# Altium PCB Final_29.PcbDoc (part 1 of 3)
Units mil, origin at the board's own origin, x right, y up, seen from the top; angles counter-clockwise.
Board outline 11000 x 6000 mil, 4 copper layers (TopLayer, MidLayer1, MidLayer2, BottomLayer), stack 29.222 mil thick; 209 components, 95 nets, 681 pads, 861 vias.
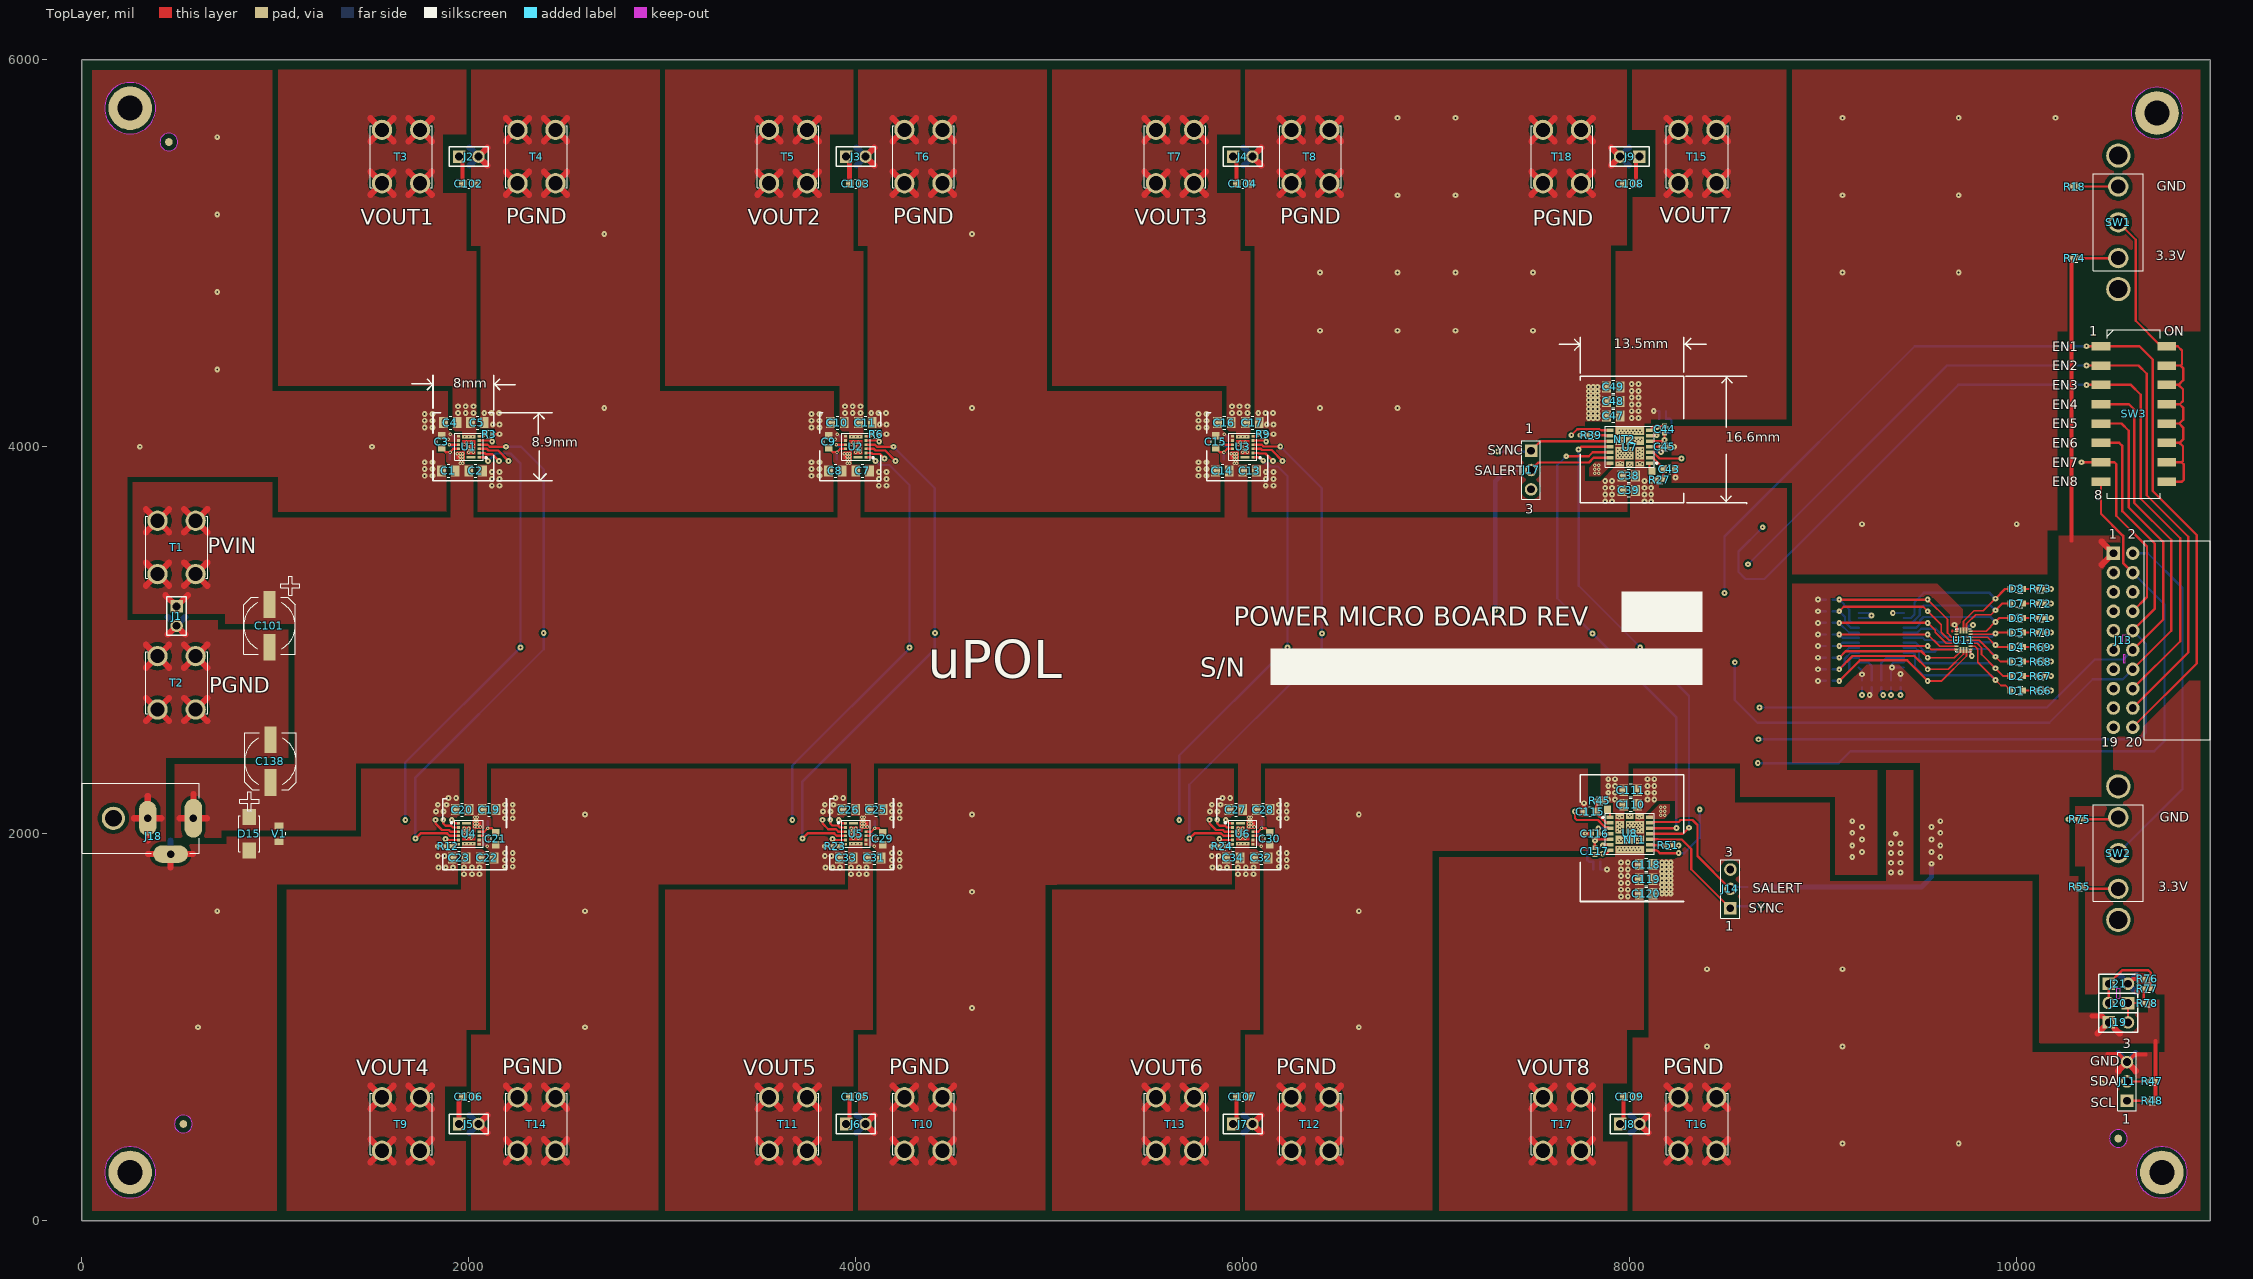
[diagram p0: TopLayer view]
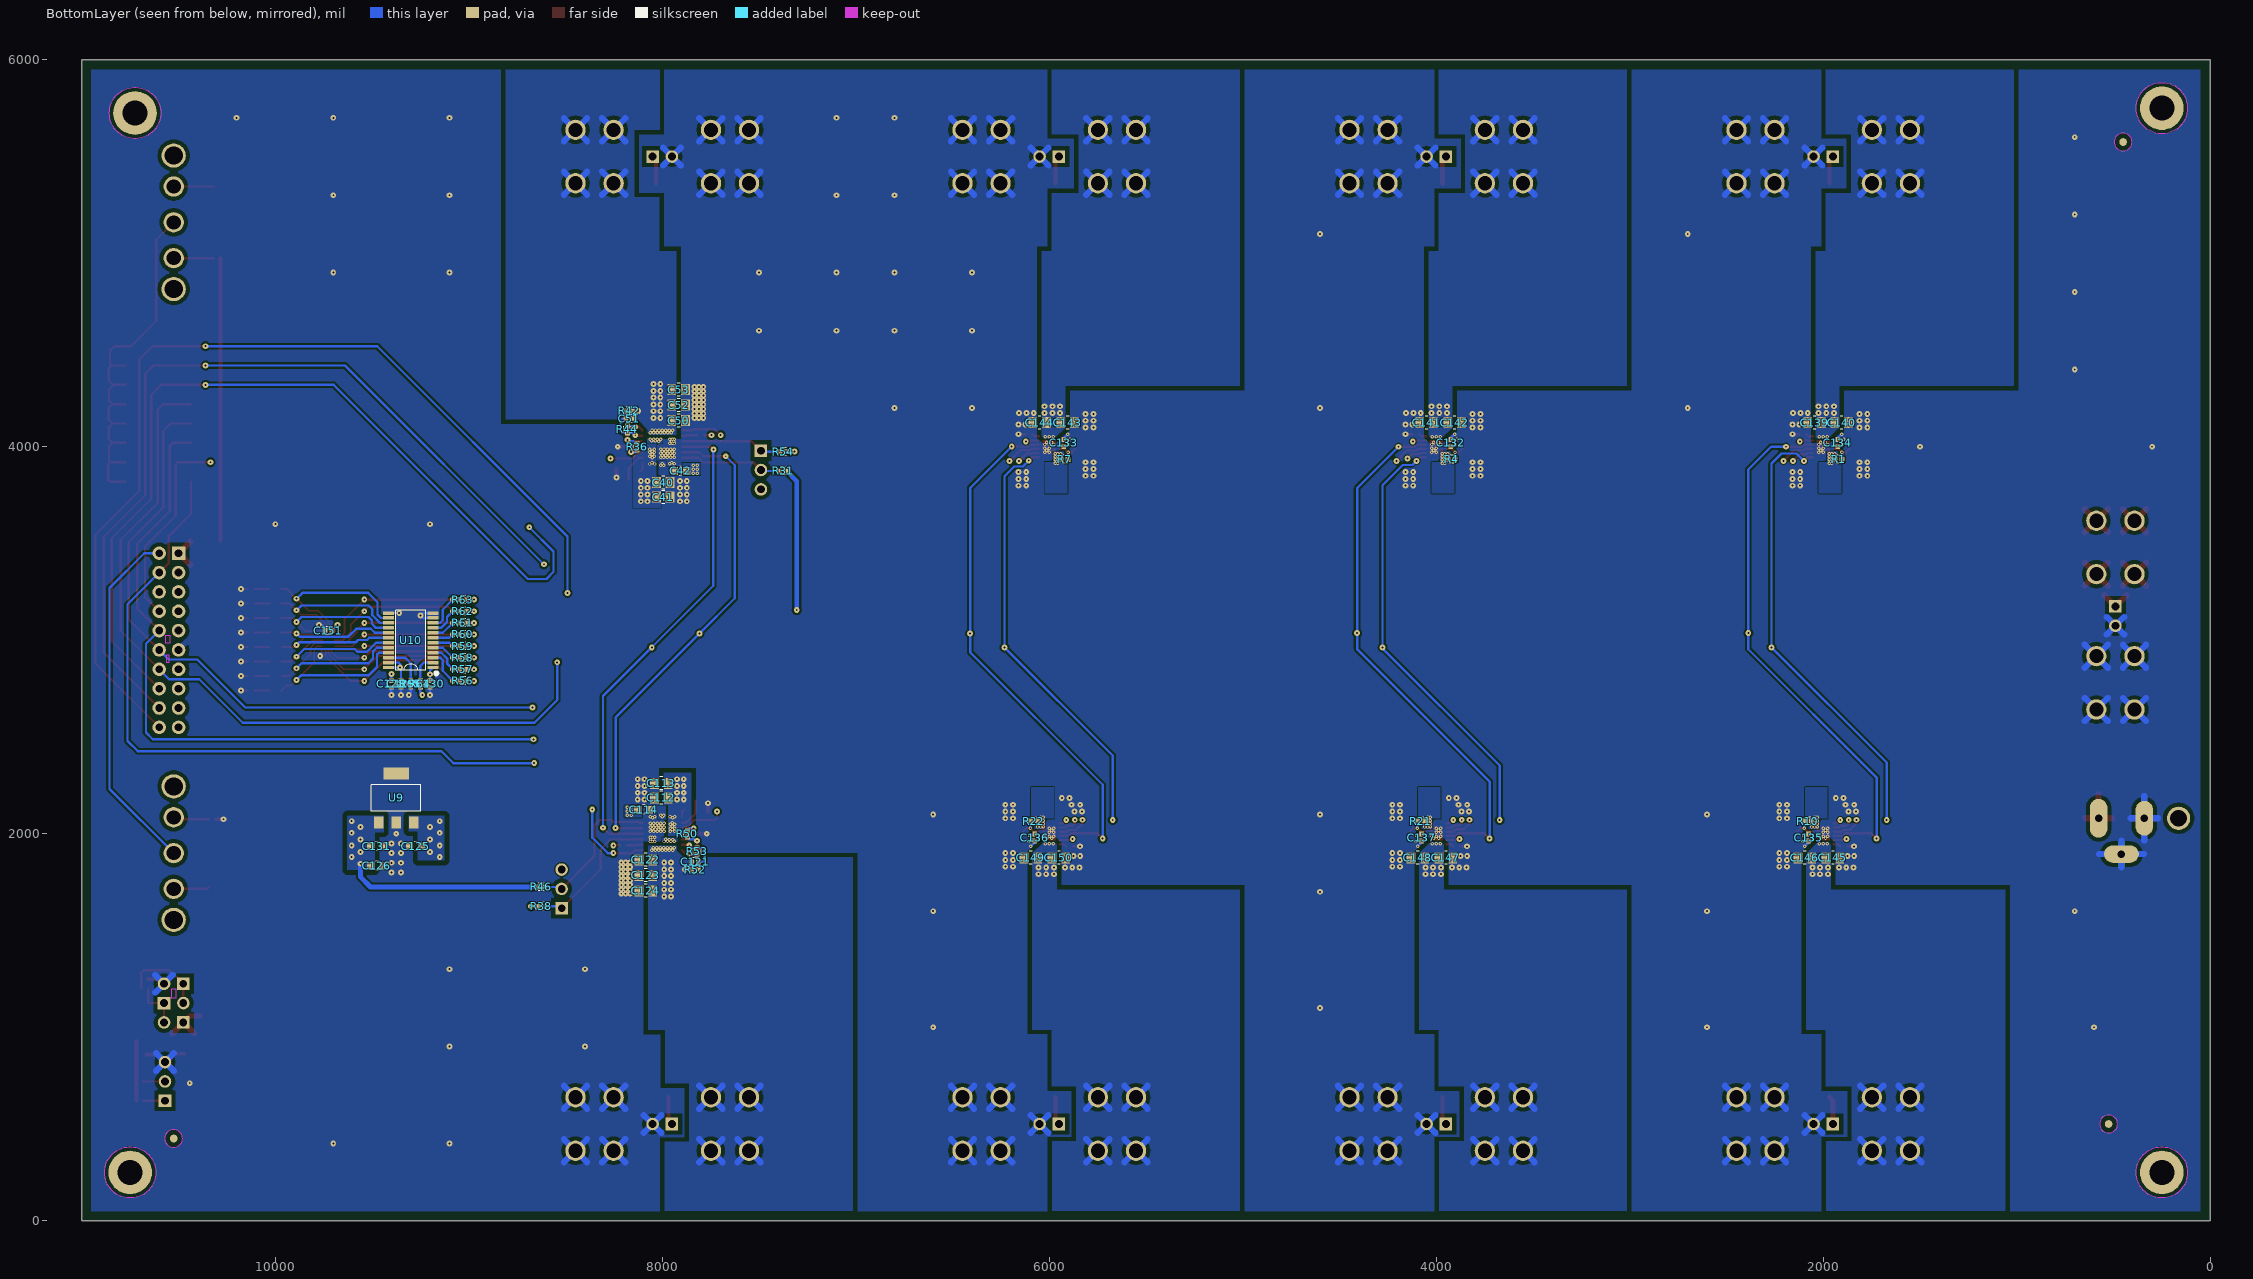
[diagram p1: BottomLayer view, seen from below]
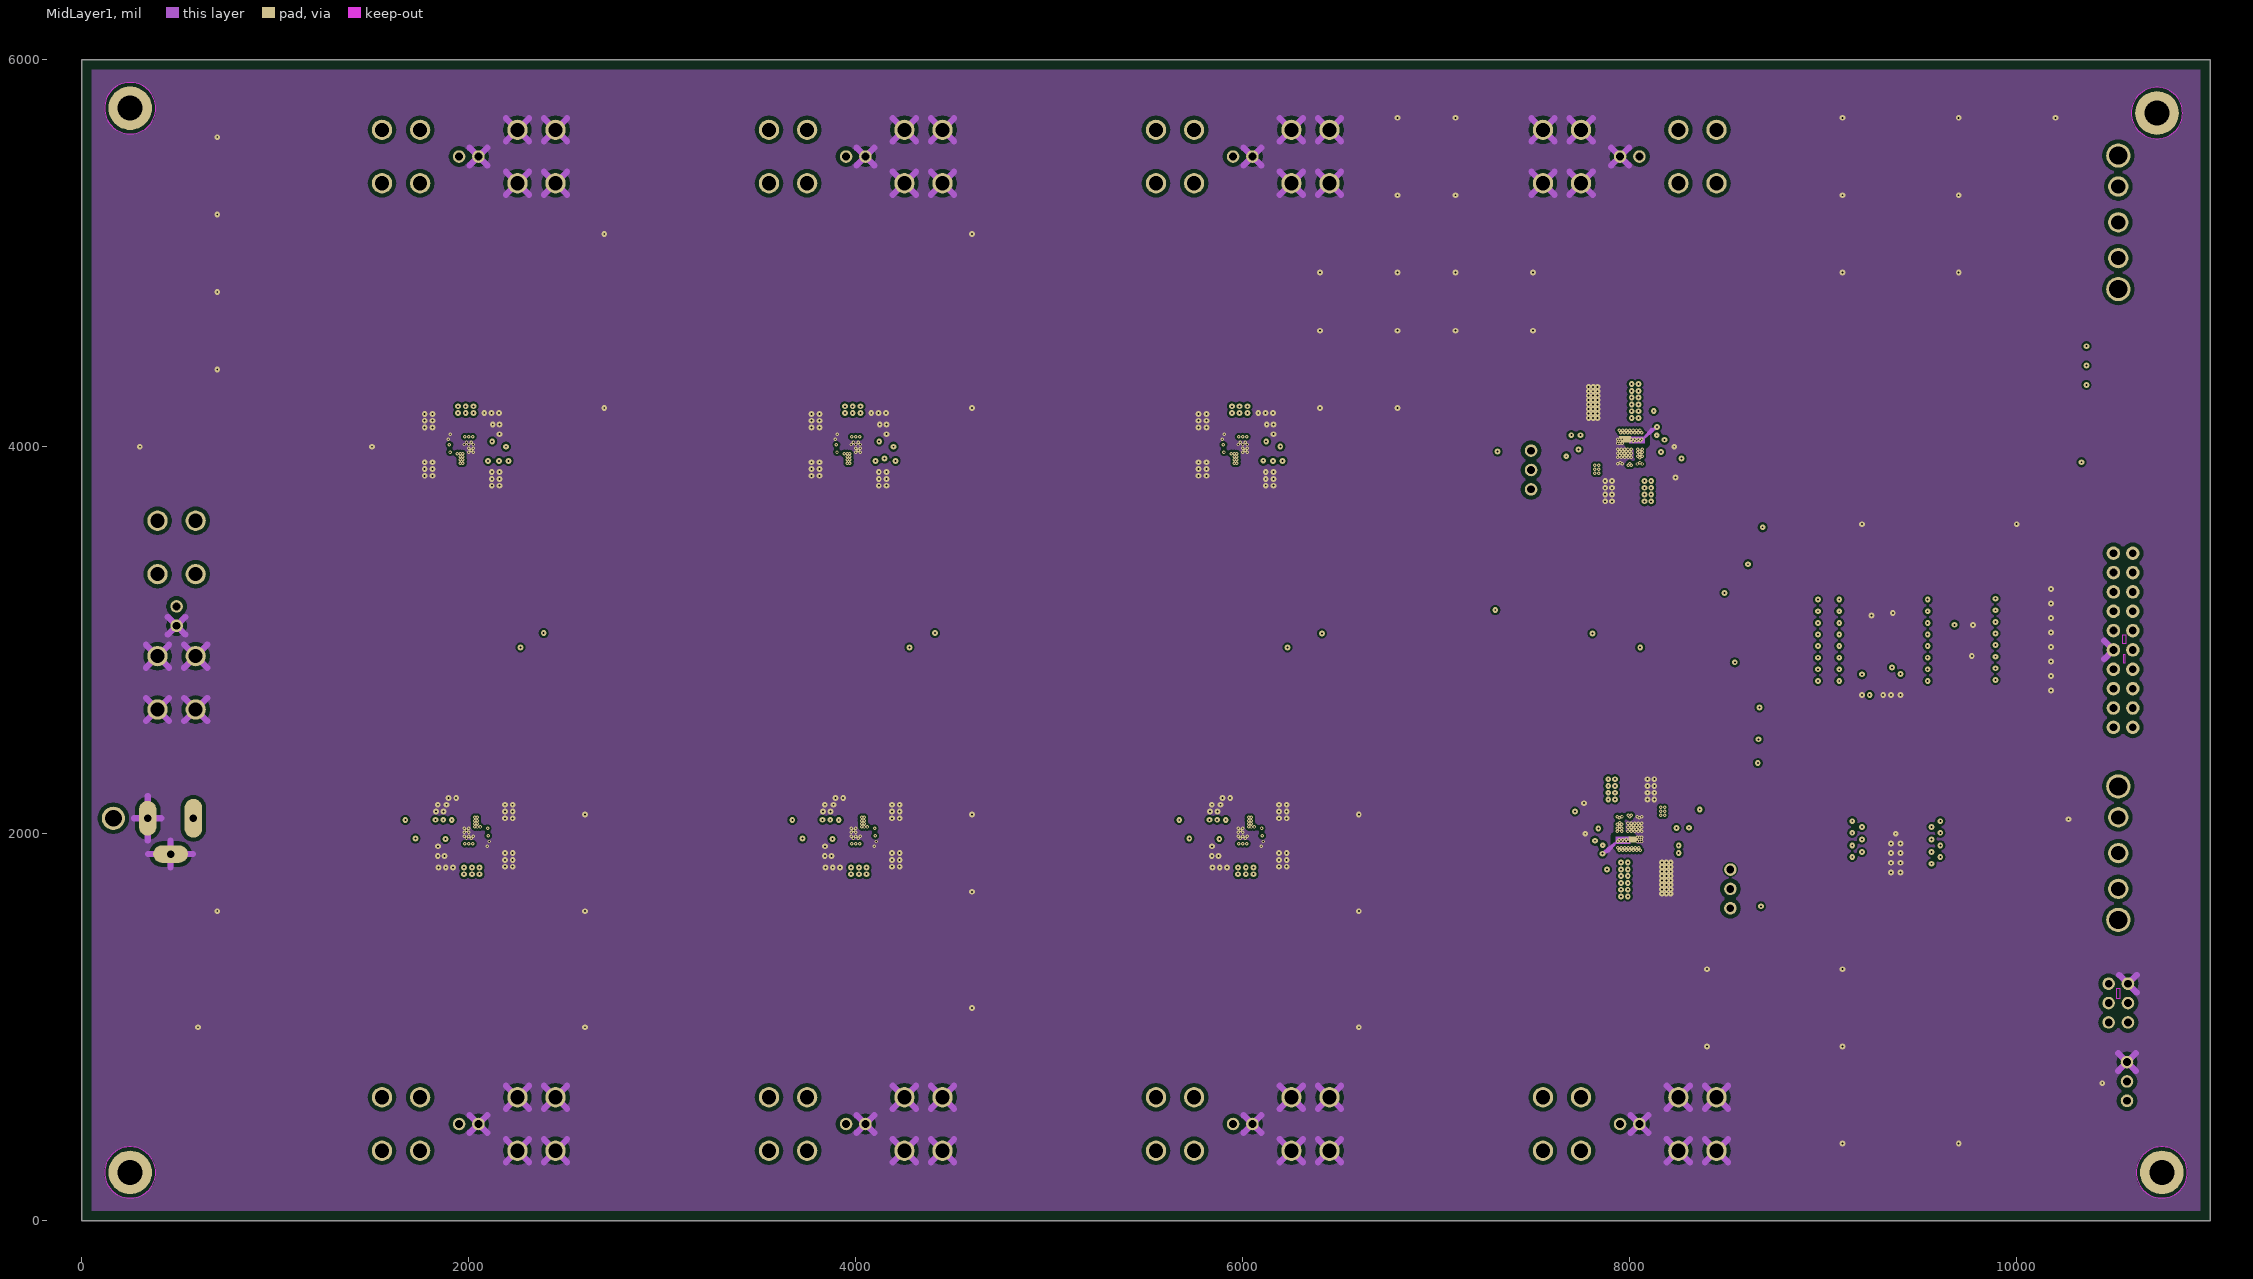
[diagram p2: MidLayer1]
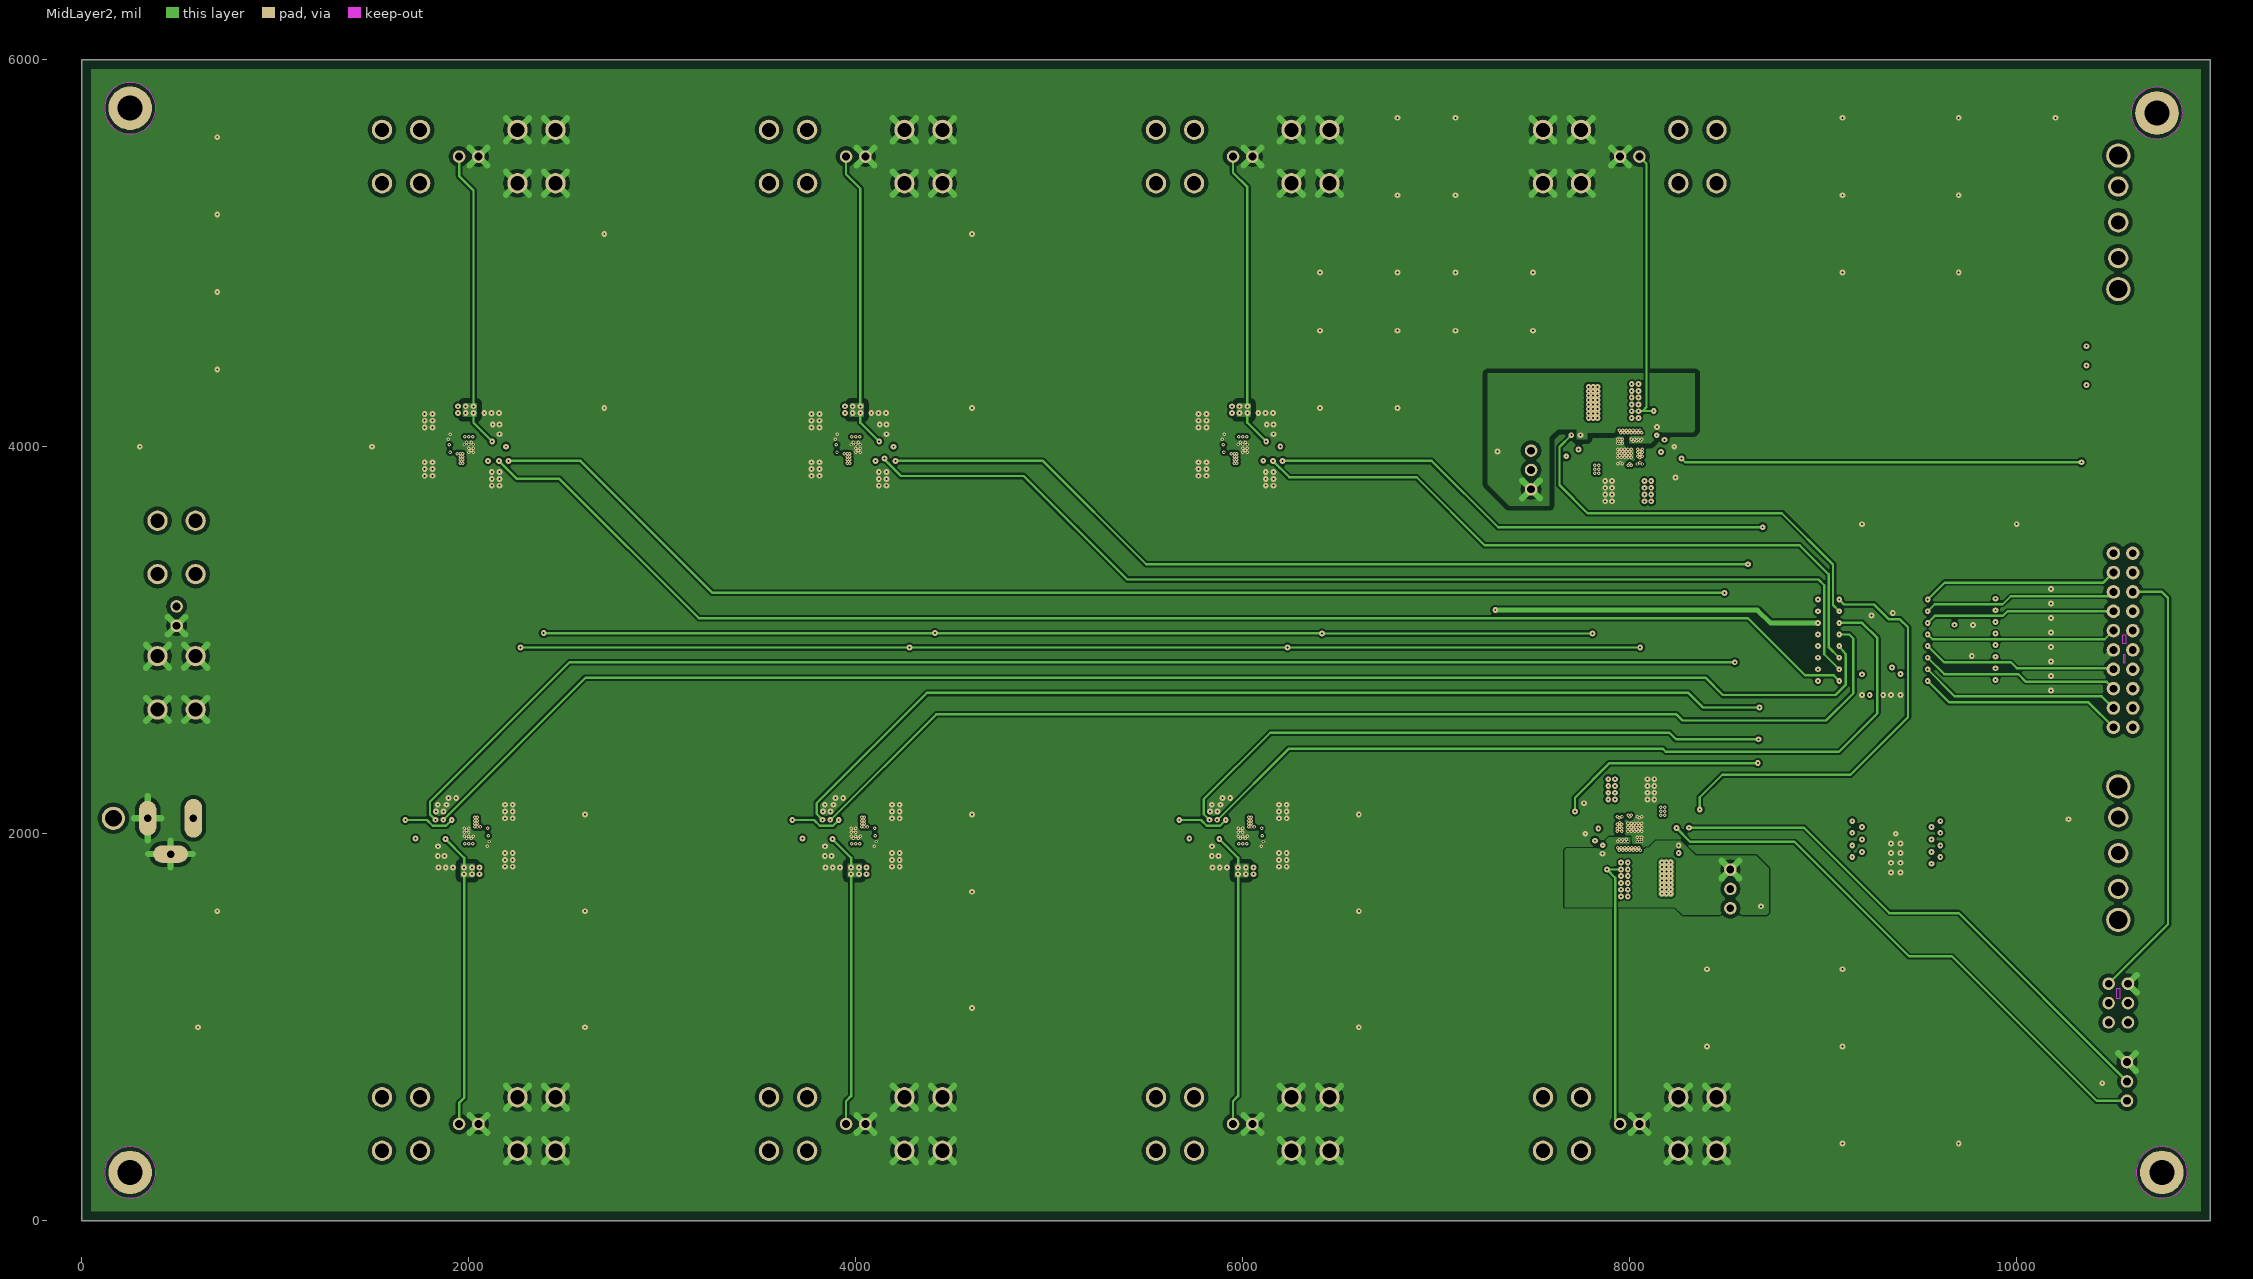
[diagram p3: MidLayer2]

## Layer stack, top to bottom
TopSolder: solder mask 0.4, Solder Resist, Dk 3.5
TopLayer: signal copper 1.4
Dielectric1: core 7.874, FR-4, Dk 4.8
MidLayer1: signal copper 1.4
Dielectric2: core 7.874, FR-4, Dk 4.8
MidLayer2: signal copper 1.4
Dielectric3: core 7.874, FR-4, Dk 4.8
BottomLayer: signal copper 1.4
BottomSolder: solder mask 0.4, Solder Resist, Dk 3.5

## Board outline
0,0 11000,0 11000,6000 0,6000

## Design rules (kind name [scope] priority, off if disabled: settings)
BoardOutlineClearance [All] p1: gap=5 ignorepadtopadclearanceinfootprint=FALSE except(0: Arc-SplitContinuation Track-SplitContinuation SMDPad-SplitContinuation THPad-SplitContinuation Via-SplitContinuation Fill-SplitContinuation Poly-SplitContinuation Region-SplitContinuation Text-SplitContinuation)
Clearance [(IsFill AND InNet('AGND1') or InNet('AGND2'))] p1: gap=6 ignorepadtopadclearanceinfootprint=TRUE except(0: Arc-Hole Track-Hole SMDPad-Hole THPad-Hole Via-Hole Fill-Hole Poly-Hole Region-Hole Text-Hole; 1: Via-Fill; 10: Via-Poly; 25: Fill-Poly)
Clearance Clearance_to_Keepout [iskeepout] p2: gap=0 ignorepadtopadclearanceinfootprint=FALSE
Clearance RELAX_TOP_Poly [Onlayer('TopLayer') vs (((WithInRoom('RELAX_AREA_1') or WithInRoom('RELAX_AREA_3') or WithInRoom('RELAX_AREA_5') or WithInRoom('RELAX_AREA_6') or WithInRoom('RELAX_AREA_7') or WithInRoom('RELAX_AREA_8') or WithInRoom('RELAX_AREA_9') or WithInRoom('RELAX_AREA_15') or WithInRoom('RELAX_AREA_17')) AND IsRegion) or ((TouchesRoom('RELAX_AREA_1') or TouchesRoom('RELAX_AREA_3') or TouchesRoom('RELAX_AREA_5') or TouchesRoom('RELAX_AREA_6') or TouchesRoom('RELAX_AREA_7') or TouchesRoom('RELAX_AREA_8') or TouchesRoom('RELAX_AREA_9') or TouchesRoom('RELAX_AREA_15') or TouchesRoom('RELAX_AREA_17')) AND InPoly))] p3 off: gap=5 ignorepadtopadclearanceinfootprint=FALSE except(0: Poly-Region; 15: THPad-Poly)
Clearance RELAX_TOP [Onlayer('TopLayer') vs (((WithInRoom('RELAX_AREA_1') or WithInRoom('RELAX_AREA_3') or WithInRoom('RELAX_AREA_5') or WithInRoom('RELAX_AREA_6') or WithInRoom('RELAX_AREA_7') or WithInRoom('RELAX_AREA_8') or WithInRoom('RELAX_AREA_9') or WithInRoom('RELAX_AREA_15') or WithInRoom('RELAX_AREA_17')) AND (InPoly = False)) or ((TouchesRoom('RELAX_AREA_1') or TouchesRoom('RELAX_AREA_3') or TouchesRoom('RELAX_AREA_5') or TouchesRoom('RELAX_AREA_6') or TouchesRoom('RELAX_AREA_7') or TouchesRoom('RELAX_AREA_8') or TouchesRoom('RELAX_AREA_9') or TouchesRoom('RELAX_AREA_15') or TouchesRoom('RELAX_AREA_17')) AND InPoly))] p4: gap=5 ignorepadtopadclearanceinfootprint=FALSE except(15: THPad-Poly)
Clearance RELAX_MID1_Poly [Onlayer('MidLayer1') vs (((WithInRoom('RELAX_AREA_17')) AND IsRegion) or ((TouchesRoom('RELAX_AREA_17')) AND InPoly))] p5: gap=8 ignorepadtopadclearanceinfootprint=FALSE except(0: Poly-Region; 10: Arc-Poly Arc-Region Track-Poly Track-Region SMDPad-Poly SMDPad-Region THPad-Region Via-Poly Via-Region Poly-Hole Region-Hole; 20: THPad-Poly; 25: Poly-Poly Region-Region)
Clearance RELAX_MID1 [Onlayer('MidLayer1') vs (((WithInRoom('RELAX_AREA_17')) AND (InPoly = False)) or ((TouchesRoom('RELAX_AREA_17')) AND InPoly))] p6: gap=8 ignorepadtopadclearanceinfootprint=FALSE except(10: Arc-Poly Arc-Region Track-Poly Track-Region SMDPad-Poly SMDPad-Region THPad-Region Via-Poly Via-Region Poly-Hole Region-Hole; 20: THPad-Poly; 25: Poly-Poly Poly-Region Region-Region)
Clearance RELAX_MID2_Poly [Onlayer('MidLayer2') vs (((WithInRoom('RELAX_AREA_17')) AND IsRegion) or ((TouchesRoom('RELAX_AREA_17')) AND InPoly))] p7: gap=8 ignorepadtopadclearanceinfootprint=FALSE except(0: Poly-Region; 10: Arc-Poly Arc-Region Track-Poly Track-Region SMDPad-Poly SMDPad-Region THPad-Region Via-Poly Via-Region Poly-Hole Region-Hole; 20: THPad-Poly; 25: Poly-Poly Region-Region)
Clearance RELAX_MID2 [Onlayer('MidLayer2') vs (((WithInRoom('RELAX_AREA_17')) AND (InPoly = False)) or ((TouchesRoom('RELAX_AREA_17')) AND InPoly))] p8: gap=8 ignorepadtopadclearanceinfootprint=FALSE except(10: Arc-Poly Arc-Region Track-Poly Track-Region SMDPad-Poly SMDPad-Region THPad-Region Via-Poly Via-Region Poly-Hole Region-Hole; 20: THPad-Poly; 25: Poly-Poly Poly-Region Region-Region)
Clearance RELAX_BOTTOM_Poly [Onlayer('BottomLayer') vs (((WithInRoom('RELAX_AREA_2') or WithInRoom('RELAX_AREA_4') or WithInRoom('RELAX_AREA_10') or WithInRoom('RELAX_AREA_11') or WithInRoom('RELAX_AREA_12') or WithInRoom('RELAX_AREA_13') or WithInRoom('RELAX_AREA_14') or WithInRoom('RELAX_AREA_16') or WithInRoom('RELAX_AREA_17')) AND IsRegion) or ((TouchesRoom('RELAX_AREA_2') or TouchesRoom('RELAX_AREA_4') or TouchesRoom('RELAX_AREA_10') or TouchesRoom('RELAX_AREA_11') or TouchesRoom('RELAX_AREA_12') or TouchesRoom('RELAX_AREA_13') or TouchesRoom('RELAX_AREA_14') or TouchesRoom('RELAX_AREA_16') or TouchesRoom('RELAX_AREA_17')) AND InPoly))] p9: gap=8 ignorepadtopadclearanceinfootprint=FALSE except(0: Poly-Region; 5: Arc-Poly Arc-Region Track-Poly Track-Region SMDPad-Poly SMDPad-Region THPad-Region Via-Poly Via-Region Poly-Poly Poly-Hole Region-Region Region-Hole; 15: THPad-Poly)
Clearance RELAX_BOTTOM [Onlayer('BottomLayer') vs (((WithInRoom('RELAX_AREA_2') or WithInRoom('RELAX_AREA_4') or WithInRoom('RELAX_AREA_10') or WithInRoom('RELAX_AREA_11') or WithInRoom('RELAX_AREA_12') or WithInRoom('RELAX_AREA_13') or WithInRoom('RELAX_AREA_14') or WithInRoom('RELAX_AREA_16') or WithInRoom('RELAX_AREA_17')) AND (InPoly = False)) or ((TouchesRoom('RELAX_AREA_2') or TouchesRoom('RELAX_AREA_4') or TouchesRoom('RELAX_AREA_10') or TouchesRoom('RELAX_AREA_11') or TouchesRoom('RELAX_AREA_12') or TouchesRoom('RELAX_AREA_13') or TouchesRoom('RELAX_AREA_14') or TouchesRoom('RELAX_AREA_16') or TouchesRoom('RELAX_AREA_17')) AND InPoly))] p10: gap=8 ignorepadtopadclearanceinfootprint=FALSE except(5: Arc-Poly Arc-Region Track-Poly Track-Region SMDPad-Poly SMDPad-Region THPad-Region Via-Poly Via-Region Poly-Poly Poly-Region Poly-Hole Region-Region Region-Hole; 15: THPad-Poly)
Clearance DEFAULT_TOP [InNetClass('DEFAULT') AND Onlayer('TopLayer')] p11: gap=8 ignorepadtopadclearanceinfootprint=FALSE except(6: SMDPad-SMDPad; 10: Arc-Poly Arc-Region Track-Poly Track-Region SMDPad-Poly SMDPad-Region THPad-Region Via-Poly Via-Region Poly-Hole Region-Hole; 20: THPad-Poly; 25: Poly-Poly Poly-Region Region-Region)
Clearance DEFAULT_MID1 [InNetClass('DEFAULT') AND Onlayer('MidLayer1')] p12: gap=8 ignorepadtopadclearanceinfootprint=FALSE except(6: SMDPad-SMDPad; 10: Arc-Poly Arc-Region Track-Poly Track-Region SMDPad-Poly SMDPad-Region THPad-Region Via-Poly Via-Region Poly-Hole Region-Hole; 20: THPad-Poly; 25: Poly-Poly Poly-Region Region-Region)
Clearance DEFAULT_MID2 [InNetClass('DEFAULT') AND Onlayer('MidLayer2')] p13: gap=8 ignorepadtopadclearanceinfootprint=FALSE except(6: SMDPad-SMDPad; 10: Arc-Poly Arc-Region Track-Poly Track-Region SMDPad-Poly SMDPad-Region THPad-Region Via-Poly Via-Region Poly-Hole Region-Hole; 20: THPad-Poly; 25: Poly-Poly Poly-Region Region-Region)
Clearance DEFAULT_BOTTOM [InNetClass('DEFAULT') AND Onlayer('BottomLayer')] p14: gap=8 ignorepadtopadclearanceinfootprint=FALSE except(6: SMDPad-SMDPad; 10: Arc-Poly Arc-Region Track-Poly Track-Region SMDPad-Poly SMDPad-Region THPad-Region Via-Poly Via-Region Poly-Hole Region-Hole; 20: THPad-Poly; 25: Poly-Poly Poly-Region Region-Region)
Clearance Clearance_default [All] p15: gap=6 ignorepadtopadclearanceinfootprint=FALSE except(0: Arc-Hole Track-Hole SMDPad-Hole THPad-Hole Via-Hole Fill-Hole Poly-Hole Region-Hole Text-Hole)
ComponentClearance Component_5mil_Clearance [All] p1: gap=0 collisioncheckmode=3 verticalgap=0 showdistances=TRUE
HoleSize [All] p1: absolutevalues=TRUE maxlimit=250 minlimit=8 maxpercent=80.000 minpercent=20.000
HoleToHoleClearance [All] p1: gap=25 allowstackedmicrovias=TRUE
MinimumAnnularRing [All] p1: minimumring=0
MinimumSolderMaskSliver [All] p1: minsoldermaskwidth=0
NetAntennae [All] p1 off: netantennaetolerance=0
PasteMaskExpansion [HasFootprint('No Footprint') And OnLayer('Top Layer')] p1: expansion=0
PolygonConnect PAD_J18-2_th_conn_TOP [(ObjectKind = 'Pad') AND (Name = 'J18-2') vs IsPoly AND Onlayer('TopLayer')] p1: connectstyle=Relief reliefconductorwidth=32 reliefentries=4 polygonreliefangle="90 Angle" airgapwidth=20
PolygonConnect PAD_J18-2_th_conn_L2 [(ObjectKind = 'Pad') AND (Name = 'J18-2') vs IsPoly AND Onlayer('MidLayer1')] p2: connectstyle=Relief reliefconductorwidth=32 reliefentries=4 polygonreliefangle="90 Angle" airgapwidth=20
PolygonConnect PAD_J18-2_th_conn_L3 [(ObjectKind = 'Pad') AND (Name = 'J18-2') vs IsPoly AND Onlayer('MidLayer2')] p3: connectstyle=Relief reliefconductorwidth=32 reliefentries=4 polygonreliefangle="90 Angle" airgapwidth=20
PolygonConnect PAD_J18-2_th_conn_BOTTOM [(ObjectKind = 'Pad') AND (Name = 'J18-2') vs IsPoly AND Onlayer('BottomLayer')] p4: connectstyle=Relief reliefconductorwidth=32 reliefentries=4 polygonreliefangle="90 Angle" airgapwidth=20
PolygonConnect PAD_J18-3_th_conn_TOP [(ObjectKind = 'Pad') AND (Name = 'J18-3') vs IsPoly AND Onlayer('TopLayer')] p5: connectstyle=Relief reliefconductorwidth=32 reliefentries=4 polygonreliefangle="90 Angle" airgapwidth=20
PolygonConnect PAD_J18-3_th_conn_L2 [(ObjectKind = 'Pad') AND (Name = 'J18-3') vs IsPoly AND Onlayer('MidLayer1')] p6: connectstyle=Relief reliefconductorwidth=32 reliefentries=4 polygonreliefangle="90 Angle" airgapwidth=20
PolygonConnect PAD_J18-3_th_conn_L3 [(ObjectKind = 'Pad') AND (Name = 'J18-3') vs IsPoly AND Onlayer('MidLayer2')] p7: connectstyle=Relief reliefconductorwidth=32 reliefentries=4 polygonreliefangle="90 Angle" airgapwidth=20
PolygonConnect PAD_J18-3_th_conn_BOTTOM [(ObjectKind = 'Pad') AND (Name = 'J18-3') vs IsPoly AND Onlayer('BottomLayer')] p8: connectstyle=Relief reliefconductorwidth=32 reliefentries=4 polygonreliefangle="90 Angle" airgapwidth=20
PolygonConnect PAD_J18-1_th_conn_TOP [(ObjectKind = 'Pad') AND (Name = 'J18-1') vs IsPoly AND Onlayer('TopLayer')] p9: connectstyle=Relief reliefconductorwidth=32 reliefentries=4 polygonreliefangle="90 Angle" airgapwidth=20
PolygonConnect PAD_J18-1_th_conn_L2 [(ObjectKind = 'Pad') AND (Name = 'J18-1') vs IsPoly AND Onlayer('MidLayer1')] p10: connectstyle=Relief reliefconductorwidth=32 reliefentries=4 polygonreliefangle="90 Angle" airgapwidth=20
PolygonConnect PAD_J18-1_th_conn_L3 [(ObjectKind = 'Pad') AND (Name = 'J18-1') vs IsPoly AND Onlayer('MidLayer2')] p11: connectstyle=Relief reliefconductorwidth=32 reliefentries=4 polygonreliefangle="90 Angle" airgapwidth=20
PolygonConnect PAD_J18-1_th_conn_BOTTOM [(ObjectKind = 'Pad') AND (Name = 'J18-1') vs IsPoly AND Onlayer('BottomLayer')] p12: connectstyle=Relief reliefconductorwidth=32 reliefentries=4 polygonreliefangle="90 Angle" airgapwidth=20
PolygonConnect Via_therm_conn_full [isvia] p13: connectstyle=Direct reliefconductorwidth=32 reliefentries=4 polygonreliefangle="90 Angle" airgapwidth=10
PolygonConnect Smd_therm_conn_full [IsPad AND (HoleDiameter = 0)] p14: connectstyle=Direct reliefconductorwidth=32 reliefentries=4 polygonreliefangle="90 Angle" airgapwidth=10
PolygonConnect Thru_therm_conn_relief [IsPad AND (HoleDiameter <> 0)] p15: connectstyle=Relief reliefconductorwidth=32 reliefentries=4 polygonreliefangle="45 Angle" airgapwidth=20
PolygonConnect Default_therm_conn [All] p16: connectstyle=Direct reliefconductorwidth=32 reliefentries=4 polygonreliefangle="45 Angle" airgapwidth=10
RoomDefinition RELAX_AREA_1 [All] p1: confinementstyle=ConfineIn formatcopy=TRUE lockcomponents=FALSE outline 1785,3775 1785,4265 2325,4265 2325,3775
RoomDefinition RELAX_AREA_2 [All] p2: confinementstyle=ConfineIn formatcopy=TRUE lockcomponents=FALSE outline 1740,4260 2230,4260 2230,3720 1740,3720
RoomDefinition RELAX_AREA_3 [All] p3: confinementstyle=ConfineIn formatcopy=TRUE lockcomponents=FALSE outline 7880,4225 8180,4225 8180,3870 7890,3870 7880,3880
RoomDefinition RELAX_AREA_4 [All] p4: confinementstyle=ConfineIn formatcopy=TRUE lockcomponents=FALSE outline 8095,4152.5 8095,4105 8135,4105 8135,4010 8160,3985 8160,3670 8100,3670 7835,3670 7835,3697.5 7835,3840 7800,3840 7800,3945 7835,3945 7835,4152.5 7835,4355 8090,4355 8095,4350
RoomDefinition RELAX_AREA_5 [All] p5: confinementstyle=ConfineIn formatcopy=TRUE lockcomponents=FALSE outline 3785,3775 3785,4265 4325,4265 4325,3775
RoomDefinition RELAX_AREA_6 [All] p6: confinementstyle=ConfineIn formatcopy=TRUE lockcomponents=FALSE outline 5785,3775 5785,4265 6325,4265 6325,3775
RoomDefinition RELAX_AREA_7 [All] p7: confinementstyle=ConfineIn formatcopy=TRUE lockcomponents=FALSE outline 1785,1775 1785,2265 2325,2265 2325,1775
RoomDefinition RELAX_AREA_8 [All] p8: confinementstyle=ConfineIn formatcopy=TRUE lockcomponents=FALSE outline 3785,1775 3785,2265 4325,2265 4325,1775
RoomDefinition RELAX_AREA_9 [All] p9: confinementstyle=ConfineIn formatcopy=TRUE lockcomponents=FALSE outline 5785,1775 5785,2265 6325,2265 6325,1775
RoomDefinition RELAX_AREA_10 [All] p10: confinementstyle=ConfineIn formatcopy=TRUE lockcomponents=FALSE outline 3740,4260 4230,4260 4230,3720 3740,3720
RoomDefinition RELAX_AREA_11 [All] p11: confinementstyle=ConfineIn formatcopy=TRUE lockcomponents=FALSE outline 5740,4260 6230,4260 6230,3720 5740,3720
RoomDefinition RELAX_AREA_12 [All] p12: confinementstyle=ConfineIn formatcopy=TRUE lockcomponents=FALSE outline 1773,2282 2263,2282 2263,1742 1773,1742
RoomDefinition RELAX_AREA_13 [All] p13: confinementstyle=ConfineIn formatcopy=TRUE lockcomponents=FALSE outline 3778,2277 4268,2277 4268,1737 3778,1737
RoomDefinition RELAX_AREA_14 [All] p14: confinementstyle=ConfineIn formatcopy=TRUE lockcomponents=FALSE outline 5779,2280 6269,2280 6269,1740 5779,1740
RoomDefinition RELAX_AREA_15 [All] p15: confinementstyle=ConfineIn formatcopy=TRUE lockcomponents=FALSE outline 9575,3125 9575,2875 9925,2875 9925,3125
RoomDefinition RELAX_AREA_16 [All] p16: confinementstyle=ConfineIn formatcopy=TRUE lockcomponents=FALSE outline 8180,2304 8180,2155 8200,2155 8200,2075 8180,2075 8180,1764 7905,1764 7905,2010 7845,2010 7840,2015 7840,2090 7840,2330 7905,2330 8180,2330
RoomDefinition RELAX_AREA_17 [All] p17: confinementstyle=ConfineIn formatcopy=TRUE lockcomponents=FALSE outline 7913,2227.5 8213,2227.5 8213,1872.5 7923,1872.5 7913,1882.5
RoutingVias [All] p1: holewidth=10 width=20 viastyle="Through Hole" minholewidth=8 minwidth=15 maxholewidth=250 maxwidth=300
SilkToSilkClearance [All] p1: silktosilkclearance=0
SilkToSolderMaskClearance [IsPad] p1: minsilkscreentomaskgap=0 clearancetoexposedcopper=TRUE
SolderMaskExpansion [HasFootprint('No Footprint') And OnLayer('Top Layer')] p1: expansion=0
Width Width_Default [All] p1: maxlimit=200 minlimit=12 preferedwidth=12
22 further rules are at their usual default settings.

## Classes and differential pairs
net class DEFAULT: 3.3V AGND1 AGND2 CTRL EN1 EN2 EN3 EN4 EN5 EN6 EN7 EN8 GPI GPIO LED1 LED2 LED3 LED4 LED5 LED6 LED7 LED8 N106541 N109036 N111800 N112773 N113813 N124020 N125365 N125599 N125833 N143732 N143740 N143880 N143888 N983153 N983255 N983335 N983701 N983781 N983905 N983923 N1133327 N1133411 N1133439 N1133683 N1133735 N1133791 N1133799 N1144589 N1166950 N1167645 N1170426 N1170926 N1170982 N1171050 N1171118 N1171178 N1171210 N1176310 N1183669 N1183969 N1197737 N1197747 N1234759 N1235035 N1235784 N1236304 N1413705 OPT PGND PGOOD1 PGOOD2 PGOOD3 PGOOD4 PGOOD5 PGOOD6 PGOOD7 PGOOD8 PVIN SALERT7 SALERT8 SCL SDA SYNC7 SYNC8 VCC3 VOUT1 VOUT2 VOUT3 VOUT4 VOUT5 VOUT6 VOUT7 VOUT8

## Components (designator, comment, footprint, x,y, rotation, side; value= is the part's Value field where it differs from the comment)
C1 "Comment" 0805#1 1895,3875 r0 top
C2 "Comment" 0805#1 2035,3875 r180 top
C3 "Comment" 0603#1 1860,4025 r270 top
C4 "Comment" 0805#1 1905,4125 r180 top
C5 "Comment" 0805#1 2045,4125 r0 top
C7 "Comment" 0805#1 4035,3875 r180 top
C8 "Comment" 0805#1 3895,3875 r0 top
C9 "Comment" 0603#1 3860,4025 r270 top
C10 "Comment" 0805#1 3905,4125 r180 top
C11 "Comment" 0805#1 4050,4125 r0 top
C13 "Comment" 0805#1 6035,3875 r180 top
C14 "Comment" 0805#1 5895,3875 r0 top
C15 "Comment" 0603#1 5860,4025 r270 top
C16 "Comment" 0805#1 5905,4125 r180 top
C17 "Comment" 0805#1 6050,4125 r0 top
C19 "Comment" 0805#1 2105,2125 r180 top
C20 "Comment" 0805#1 1965,2125 r0 top
C21 "Comment" 0603#1 2140,1975 r90 top
C22 "Comment" 0805#1 2095,1875 r0 top
C23 "Comment" 0805#1 1950,1875 r180 top
C25 "Comment" 0805#1 4105,2125 r180 top
C26 "Comment" 0805#1 3965,2125 r0 top
C27 "Comment" 0805#1 5965,2125 r0 top
C28 "Comment" 0805#1 6105,2125 r180 top
C29 "Comment" 0603#1 4140,1975 r90 top
C30 "Comment" 0603#1 6140,1975 r90 top
C31 "Comment" 0805#1 4095,1875 r0 top
C32 "Comment" 0805#1 6095,1875 r0 top
C33 "Comment" 0805#1 3950,1875 r180 top
C34 "Comment" 0805#1 5950,1875 r180 top
C38 "Comment" 0805#1 7995,3850 r0 top
C39 "Comment" 0805#1 7995,3775 r0 top
C40 "Comment" 0805#2 7995,3815 r180 bottom
C41 "Comment" 0805#2 7995,3740 r180 bottom
C42 "Comment" 0603#2 7905,3875 r180 bottom
C43 "Comment" 0603#1 8205,3885 r180 top
C44 "Comment" 0402#1 8180,4090 r270 top
C45 "Comment" 0402#1 8180,4000 r180 top
C47 "Comment" 0805#1 7915,4160 r180 top
C48 "Comment" 0805#1 7915,4235 r180 top
C49 "Comment" 0805#1 7915,4310 r180 top
C50 "Comment" 0805#2 7915,4135 r0 bottom
C51 "Comment" 0402#2 8170,4145 r180 bottom
C52 "Comment" 0805#2 7915,4215 r0 bottom
C53 "Comment" 0805#2 7915,4295 r0 bottom
C101 "Comment" C10_CAP 970,3075 r270 top
C102 "Comment" 0603#1 2000,5360 r180 top
C103 "Comment" 0603#1 4000,5360 r180 top
C104 "Comment" 0603#1 6000,5360 r180 top
C105 "Comment" 0603#1 4000,640 r180 top
C106 "Comment" 0603#1 2000,640 r180 top
C107 "Comment" 0603#1 6000,640 r180 top
C108 "Comment" 0603#1 8000,5360 r0 top
C109 "Comment" 0603#1 8000,640 r180 top
C110 "Comment" 0805#1 8005,2150 r180 top
C111 "Comment" 0805#1 8005,2225 r180 top
C112 "Comment" 0805#2 8005,2185 r0 bottom
C113 "Comment" 0805#2 8005,2260 r0 bottom
C114 "Comment" 0603#2 8095,2125 r0 bottom
C115 "Comment" 0603#1 7795,2115 r0 top
C116 "Comment" 0402#1 7820,2000 r0 top
C117 "Comment" 0402#1 7820,1910 r90 top
C118 "Comment" 0805#1 8085,1840 r0 top
C119 "Comment" 0805#1 8085,1765 r0 top
C120 "Comment" 0805#1 8085,1690 r0 top
C121 "Comment" 0402#2 7830,1855 r0 bottom
C122 "Comment" 0805#2 8085,1865 r180 bottom
C123 "Comment" 0805#2 8085,1785 r180 bottom
C124 "Comment" 0805#2 8085,1705 r180 bottom
C125 "Comment" 0603#2 9275,1935 r0 bottom
C126 "Comment" 0603#2 9475,1835 r180 bottom
C128 "Comment" 0402#1 9400,2775 r90 bottom
C129 "Comment" 0402#1 9350,2775 r90 bottom
C130 "Comment" 0402#1 9200,2775 r90 bottom
C131 "Comment" 0603#2 9475,1935 r180 bottom
C132 "Comment" 0402#1 3925,4020 r270 bottom
C133 "Comment" 0402#1 5925,4020 r270 bottom
C134 "Comment" 0402#1 1925,4020 r270 bottom
C135 "Comment" 0402#1 2075,1980 r90 bottom
C136 "Comment" 0402#1 6075,1980 r90 bottom
C137 "Comment" 0402#1 4075,1980 r90 bottom
C138 "Comment" C10_CAP 975,2375 r90 top
C139 "Comment" 0805#2 2045,4125 r180 bottom
C140 "Comment" 0805#2 1905,4125 r0 bottom
C141 "Comment" 0805#2 4050,4125 r180 bottom
C142 "Comment" 0805#2 3905,4125 r0 bottom
C143 "Comment" 0805#2 5905,4125 r0 bottom
C144 "Comment" 0805#2 6050,4125 r180 bottom
C145 "Comment" 0805#2 1950,1875 r0 bottom
C146 "Comment" 0805#2 2095,1875 r180 bottom
C147 "Comment" 0805#2 3950,1875 r0 bottom
C148 "Comment" 0805#2 4095,1875 r180 bottom
C149 "Comment" 0805#2 6095,1875 r180 bottom
C150 "Comment" 0805#2 5950,1875 r0 bottom
C151 "Comment" 0402#2 9725,3050 r180 bottom
D1 "Comment" SML-LX0603 10000,2740 r180 top
D2 "Comment" SML-LX0603 10000,2815 r180 top
D3 "Comment" SML-LX0603 10000,2890 r180 top
D4 "Comment" SML-LX0603 10000,2965 r180 top
D5 "Comment" SML-LX0603 10000,3040 r180 top
D6 "Comment" SML-LX0603 10000,3115 r180 top
D7 "Comment" SML-LX0603 10000,3190 r180 top
D8 "Comment" SML-LX0603 10000,3265 r180 top
D15 "Comment" DO-214AC_BI 865,2000 r270 top
J1 "Comment" HDR1X2 490,3125 r270 top
J2 "Comment" HDR1X2 2000,5500 r0 top
J3 "Comment" HDR1X2 4000,5500 r0 top
J4 "Comment" HDR1X2 6000,5500 r0 top
J5 "Comment" HDR1X2 2000,500 r0 top
J6 "Comment" HDR1X2 4000,500 r0 top
J7 "Comment" HDR1X2 6000,500 r0 top
J8 "Comment" HDR1X2 8000,500 r0 top
J9 "Comment" HDR1X2 8000,5500 r180 top
J11 "Comment" HDR1X3 10570,720 r90 top
J13 "Comment" SSQ-110-02-T-D-RA 10550,3000 r270 top
J14 "Comment" HDR1X3 8520,1715 r90 top
J17 "Comment" HDR1X3 7490,3880 r270 top
J18 "Comment" PJ-058A 458.6,2080 r270 top
J19 "Comment" HDR1X2 10525,1025 r0 top
J20 "Comment" HDR1X2 10525,1125 r180 top
J21 "Comment" HDR1X2 10525,1225 r0 top
NT1 "Comment" "NET TIE 32 X 62" 8011,1970 r0 top net-tie
NT2 "Comment" "NET TIE 32 X 62" 7960,4039 r0 top net-tie
R1 "Comment" 0402#2 1920,3935 r180 bottom
R3 "Comment" 0402#1 2105,4065 r180 top
R4 "Comment" 0402#2 3920,3935 r180 bottom
R6 "Comment" 0402#1 4105,4065 r180 top
R7 "Comment" 0402#2 5920,3935 r180 bottom
R9 "Comment" 0402#1 6105,4065 r180 top
R10 "Comment" 0402#2 2080,2065 r0 bottom
R12 "Comment" 0402#1 1895,1935 r0 top
R18 "Comment" 0402#1 10300,5345 r180 top
R21 "Comment" 0402#2 4080,2065 r0 bottom
R22 "Comment" 0402#2 6080,2065 r0 bottom
R23 "Comment" 0402#1 3895,1935 r0 top
R24 "Comment" 0402#1 5895,1935 r0 top
R27 "Comment" 0402#1 8155,3830 r0 top
R31 "Comment" 0402#2 7375,3875 r0 bottom
R36 "Comment" 0402#1 8130,4000 r270 bottom
R38 "Comment" 0402#2 8625,1625 r180 bottom
R39 "Comment" 0402#1 7800,4060 r180 top
R42 "Comment" 0402#2 8170,4185 r180 bottom
R44 "Comment" 0402#1 8180,4090 r270 bottom
R45 "Comment" 0402#1 7845,2170 r180 top
R46 "Comment" 0402#2 8625,1725 r180 bottom
R47 "Comment" 0402#1 10700,720 r0 top
R48 "Comment" 0402#1 10700,620 r0 top
R50 "Comment" 0402#1 7870,2000 r90 bottom
R51 "Comment" 0402#1 8200,1940 r0 top
R52 "Comment" 0402#2 7830,1815 r0 bottom
R53 "Comment" 0402#1 7820,1910 r90 bottom
R54 "Comment" 0402#2 7375,3975 r0 bottom
R55 "Comment" 0402#1 10325,1725 r180 top
R56 "Comment" 0402#2 9030,2790 r0 bottom
R57 "Comment" 0402#2 9030,2850 r0 bottom
R58 "Comment" 0402#2 9030,2910 r180 bottom
R59 "Comment" 0402#2 9030,2970 r0 bottom
R60 "Comment" 0402#2 9030,3030 r0 bottom
R61 "Comment" 0402#2 9030,3090 r0 bottom
R62 "Comment" 0402#2 9030,3150 r180 bottom
R63 "Comment" 0402#2 9030,3210 r0 bottom
R64 "Comment" 0402#1 9250,2775 r270 bottom
R65 "Comment" 0402#1 9300,2775 r90 bottom
R66 "Comment" 0402#1 10125,2740 r180 top
R67 "Comment" 0402#1 10125,2815 r180 top
R68 "Comment" 0402#1 10125,2890 r180 top
R69 "Comment" 0402#1 10125,2965 r180 top
R70 "Comment" 0402#1 10125,3040 r180 top
R71 "Comment" 0402#1 10125,3115 r180 top
R72 "Comment" 0402#1 10125,3190 r180 top
R73 "Comment" 0402#1 10125,3265 r180 top
R74 "Comment" 0402#1 10300,4975 r180 top
R75 "Comment" 0402#1 10325,2075 r180 top
R76 "Comment" 0402#1 10675,1250 r180 top
R77 "Comment" 0402#1 10675,1200 r0 top
R78 "Comment" 0402#1 10675,1125 r180 top
SW1 "Comment" 1101M1S3CQE2 10525,5160 r0 top
SW2 "Comment" 1101M1S3CQE2 10525,1900 r0 top
SW3 "Comment" 219-8MST 10605,4170 r270 top
T1 "Comment" 7693 490,3480 r0 top
T2 "Comment" 7693 490,2780 r0 top
T3 "Comment" 7693 1650,5500 r0 top
T4 "Comment" 7693 2350,5500 r0 top
T5 "Comment" 7693 3650,5500 r0 top
T6 "Comment" 7693 4350,5500 r0 top
T7 "Comment" 7693 5650,5500 r0 top
T8 "Comment" 7693 6350,5500 r0 top
T9 "Comment" 7693 1650,500 r0 top
T10 "Comment" 7693 4350,500 r0 top
T11 "Comment" 7693 3650,500 r0 top
T12 "Comment" 7693 6350,500 r0 top
T13 "Comment" 7693 5650,500 r0 top
T14 "Comment" 7693 2350,500 r0 top
T15 "Comment" 7693 8350,5500 r0 top
T16 "Comment" 7693 8350,500 r0 top
T17 "Comment" 7693 7650,500 r0 top
T18 "Comment" 7693 7650,5500 r0 top
U1 "Comment" FS1406-02_NEW 2000,4000 r180 top
U2 "Comment" FS1406-02_NEW 4000,4000 r180 top
U3 "Comment" FS1406-02_NEW 6000,4000 r180 top
U4 "Comment" FS1406-02_NEW 2000,2000 r0 top
U5 "Comment" FS1406-02_NEW 4000,2000 r0 top
U6 "Comment" FS1406-02_NEW 6000,2000 r0 top
U7 "Comment" FS1412-POD 8000,4000 r180 top locked
U8 "Comment" FS1412-POD 8000,2000 r0 top
U9 "Comment" SOT223 9375,2185 r0 bottom
U10 "Comment" SOP65P640X120-24N 9300,3000 r90 bottom
U11 "Comment" STQFN20 9725,3000 r0 top locked
V1 "Comment" AVR 1020,2000 r90 top

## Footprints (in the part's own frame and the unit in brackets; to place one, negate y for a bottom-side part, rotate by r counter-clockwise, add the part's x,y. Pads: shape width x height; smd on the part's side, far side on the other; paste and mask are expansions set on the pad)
219-8MST [mil] "219-8MST"
  rect 44x96 smd paste+0 mask+2: 1(-350,-169.5) 2(-250,-169.5) 3(-150,-169.5) 4(-50,-169.5) 5(50,-169.5) 6(150,-169.5) 7(250,-169.5) 8(350,-169.5) 9(350,169.5) 10(250,169.5) 11(150,169.5) 12(50,169.5) 13(-50,169.5) 14(-150,169.5) 15(-250,169.5) 16(-350,169.5)
  silkscreen extent -435,-137 435,137, body extent -372,-218 372,218, height 39
0402#1 [mil] "0402"
  rect 25.6x25.6 smd paste+0 mask+2: 1(-17.7,0) 2(17.7,0)
  silkscreen extent -15,-20 15,20, body extent -31,-13 31,13, height 39
0402#2 [mil] "0402"
  rect 25.6x25.6 smd paste+0 mask+2: 1(17.7,0) 2(-17.7,0)
  silkscreen extent -15,-20 15,20, body extent -30,-13 30,13, height 39
0603#1 [mil] "0603"
  rect 37.4x39.4 smd paste+0 mask+2: 1(-31.5,0) 2(31.5,0)
  silkscreen extent -6,-24 6,24, body extent -50,-20 50,20, height 39
0603#2 [mil] "0603"
  rect 37.4x39.4 smd paste+0 mask+2: 1(31.5,0) 2(-31.5,0)
  silkscreen extent -6,-24 6,24, body extent -50,-20 50,20, height 39
0805#1 [mil] "0805"
  rect 45.3x57.1 smd paste+0 mask+2: 1(-35.5,0) 2(35.5,0)
  silkscreen extent -7,-34 7,34, body extent -58,-29 58,29, height 39
0805#2 [mil] "0805"
  rect 45.3x57.1 smd paste+0 mask+2: 1(35.5,0) 2(-35.5,0)
  silkscreen extent -7,-34 7,34, body extent -58,-29 58,29, height 39
1101M1S3CQE2 [mil] "1101M1S3CQE2"
  round 105 hole 73 paste+0 mask+2: 1(0,-185) 2(0,0) 3(0,185)
  round 125 hole 94 paste+0 mask+2: SH1(0,345) SH2(0,-345)
  silkscreen extent -130,-250 130,250, body extent -62,-408 62,408, height 39
7693 [mil] "7693"
  round 105 hole 73 paste+0 mask+2: 1(-98.5,138) 2(-98.5,-138) 3(98.5,-138) 4(98.5,138)
  silkscreen extent -160,-160 160,160, body extent -151,-190 151,190, height 39
AVR [mil] "AVR"
  rect 35.4x47.2 smd paste+0 mask+2: 1(-41.3,0) 2(41.3,0)
  silkscreen extent -7,-34 7,34, body extent -59,-24 59,24, height 39
C10_CAP [mil] "C10_CAP"
  rect 137.8x63 smd paste+0 mask+2: 1(-110.2,0) 2(110.2,0)
  silkscreen extent -256,-134 148,157, body extent -142,-69 142,69, height 39
DO-214AC_BI [mil] "DO-214AC_BI"
  rect 82.7x70.9 smd paste+0 mask+2: 1(86.6,0) 2(-86.6,0)
  silkscreen extent -93,-55 93,55, body extent -128,-35 128,35, height 39
FS1406-02_NEW [mil] "FS1406-02_NEW"
  rect 17.7x13.8 smd paste-1 mask+1.95: 1(-53.1,54.1) 2(-53.1,32.5) 3(-53.1,10.8) 4(-53.1,-10.8) 5(-53.1,-32.5) 6(-53.1,-54.1) 8(53.1,-54.1) 9(53.1,-32.5) 10(53.1,-10.8) 11(53.1,10.8)
  rect 68.9x17.7 smd paste-10000 mask+2.95: 7(0,-52.2)
  rect 7.9x7.9 smd paste-10000 mask-10000: 12(31.5,51.2) 13(51.2,51.2) 14(31.5,35.4) 16(0,0) 17(51.2,35.4)
  rect 45.3x13.8 smd paste-2 mask+2.95: 15(-11.8,54.1)
  TopLayer region: -34.4,-33.5 -34.4,37.4 10.8,37.4 10.8,-2 34.4,-2 34.4,-33.5
  TopLayer region: 20.7,61 62,61 62,25.6 34.4,25.6 34.4,7.9 20.7,7.9
  silkscreen extent -94,-71 74,71, body extent -62,-61 62,77, height 39
FS1412-POD [mil] "FS1412-POD"
  rect 37.4x19.7 smd paste-3.95 mask-1.95: 1(-102.4,85.6) 2(-102.4,57.1) 3(-102.4,28.5) 4(-102.4,0) 5(-102.4,-28.5) 6(-102.4,-57.1) 7(-102.4,-85.6) 9(102.4,-85.6) 10(102.4,-57.1) 11(102.4,-28.5) 12(102.4,0) 13(102.4,28.5) 14(102.4,57.1) 15(102.4,85.6)
  rect 147.6x39.4 smd paste-10000 mask-1.95: 8(0,-81.7)
  rect 45.3x25.6 smd paste-4.95 mask-2: 16(51.2,88.6) 18(-51.2,88.6)
  rect 37.4x25.6 smd paste-4.95 mask-1.95: 17(0,88.6)
  rect 45.3x65 smd paste-10000 mask-2: 19(-51.2,33.5)
  rect 45.3x43.3 smd paste-5.9 mask-2: 20(51.2,-30.5)
  rect 92.5x65 smd paste-10000 mask-1.95: 21(27.6,33.5)
  rect 92.5x43.3 smd paste-10000 mask-1.95: 22(-27.6,-30.5)
  silkscreen extent -145,-107 126,107, body extent -121,-156 121,101, height 39
HDR1X2 [mil] "HDR1X2"
  rect 65x65 / inner round 65 / far side rect 65x65 hole 40 paste+0 mask+2: 1(-50,0)
  round 65 hole 40 paste+0 mask+2: 2(50,0)
  silkscreen extent -100,-50 100,50, body extent -82,-33 82,33, height 39
HDR1X3 [mil] "HDR1X3"
  rect 65x65 / inner round 65 / far side rect 65x65 hole 40 paste+0 mask+2: 1(-100,0)
  round 65 hole 40 paste+0 mask+2: 2(0,0) 3(100,0)
  silkscreen extent -151,-49 151,49, body extent -132,-33 132,33, height 39
"NET TIE 32 X 62" [mil]
  rect 33x32 on Mid1 mask+10: 1(0,0) 2(30,0)
PJ-058A [mil] "PJ-058A"
  round 120 hole 87 paste+0 mask+2: 0(0,-295.3)
  oval 200x90 hole 39 paste+0 mask+2: 1(0,118.1)
  oval 180x90 hole 39 paste+0 mask+2: 2(0,-118.1)
  oval 90x180 hole 39 paste+0 mask+2: 3(185,0)
  silkscreen extent -181,-457 181,150, body extent -100,-355 230,163, height 39
SML-LX0603 [mil] "SML-LX0603"
  rect 31.5x31.5 smd paste+0 mask+2: 1(31.5,0) 2(-31.5,0)
  silkscreen extent -32,-22 9,23, body extent -47,-16 47,16, height 39
SOP65P640X120-24N [mil] "SOP65P640X120-24N"
  rect 18x57 smd paste+0 mask+1: 1(-140.7,-116.1) 2(-115.2,-116.1) 3(-89.6,-116.1) 4(-64,-116.1) 5(-38.4,-116.1) 6(-12.8,-116.1) 7(12.8,-116.1) 8(38.4,-116.1) 9(64,-116.1) 10(89.6,-116.1) 11(115.2,-116.1) 12(140.7,-116.1) 13(140.7,116.1) 14(115.2,116.1) 15(89.6,116.1) 16(64,116.1) 17(38.4,116.1) 18(12.8,116.1) 19(-12.8,116.1) 20(-38.4,116.1) 21(-64,116.1) 22(-89.6,116.1) 23(-115.2,116.1) 24(-140.7,116.1)
  silkscreen extent -179,-140 155,77, body extent -150,-145 150,145, height 39
SOT223 [mil] "SOT223"
  rect 47.2x63 smd paste+0 mask+2: 1(90.6,126) 2(0,126) 3(-90.6,126)
  rect 129.9x63 smd paste+0 mask+2: 4(0,-126)
  silkscreen extent -128,-69 128,69, body extent -114,-158 114,158, height 39
SSQ-110-02-T-D-RA [mil] "SSQ-110-02-T-D-RA"
  rect 70x70 / inner round 70 / far side rect 70x70 hole 40 paste+0 mask+2: 1(-450,-50)
  round 70 hole 40 paste+0 mask+2: 2(-450,50) 3(-350,-50) 4(-350,50) 5(-250,-50) 6(-250,50) 7(-150,-50) 8(-150,50) 9(-50,-50) 10(-50,50) 11(50,-50) 12(50,50) 13(150,-50) 14(150,50) 15(250,-50) 16(250,50) 17(350,-50) 18(350,50) 19(450,-50) 20(450,50)
  silkscreen extent -515,110 515,450, body extent -485,-85 485,85, height 39
STQFN20 [mil] "STQFN20"
  rect 19.1x9.1 smd paste+0 mask+2: 1(-35.7,47.2) 2(-35.7,31.5) 6(-35.7,-31.5) 7(-35.7,-47.2) 11(35.7,-47.2) 12(35.7,-31.5) 16(35.7,31.5) 17(35.7,47.2)
  rect 38.4x9.1 smd paste+0 mask+2: 3(-26.1,15.7)
  rect 30.5x9.1 smd paste+0 mask+2: 4(-30,0) 5(-30,-15.7) 13(30,-15.7) 14(30,0) 15(30,15.7)
  rect 9.1x30.5 smd paste+0 mask+2: 8(-15.7,-49.7) 9(0,-49.7) 10(15.7,-49.7) 18(15.7,49.7) 19(0,49.7) 20(-15.7,49.7)
  TopLayer circle w5.9: c-58,47 r4.11
  silkscreen extent -40,-60 40,60, body extent -40,-65 40,65, height 39

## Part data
C1 C2 C4 C5 C7 C8 C10 C11 C13 C14 C16 C17 C19 C20 C22 C23 C25 C26 C27 C28 C31 C32 C33 C34 C38 C39 C40 C41 C47 C48 C49 C50 C52 C53 C110 C111 C112 C113 C118 C119 C120 C122 C123 C124 C139 C140 C141 C142 C143 C144 C145 C146 C147 C148 C149 C150: library part 0805
C3 C9 C15 C21 C29 C30 C42 C43 C102 C103 C104 C105 C106 C107 C108 C109 C114 C115 C125 C126 C131: library part 0603
C44 C45 C51 C116 C117 C121 C128 C129 C130 C132 C133 C134 C135 C136 C137 C151 R1 R3 R4 R6 R7 R9 R10 R12 R18 R21 R22 R23 R24 R27 R31 R36 R38 R39 R42 R44 R45 R46 R47 R48 R50 R51 R52 R53 R54 R55 R56 R57 R58 R59 R60 R61 R62 R63 R64 R65 R66 R67 R68 R69 R70 R71 R72 R73 R74 R75 R76 R77 R78: library part 0402
C101 C138: library part C10_CAP
D1 D2 D3 D4 D5 D6 D7 D8: library part SML-LX0603
D15: library part DO-214AC_BI
J1 J2 J3 J4 J5 J6 J7 J8 J9 J19 J20 J21: library part HDR1X2
J11 J14 J17: library part HDR1X3
J13: library part SSQ-110-02-T-D-RA
J18: library part PJ-058A
SW1 SW2: library part 1101M1S3CQE2
SW3: library part 219-8MST
T1 T2 T3 T4 T5 T6 T7 T8 T9 T10 T11 T12 T13 T14 T15 T16 T17 T18: library part 7693
U1 U2 U3 U4 U5 U6: library part FS1406-02_NEW
U7 U8: library part FS1412-POD
U9: library part SOT223
U10: library part SOP65P640X120-24N
U11: library part STQFN20
V1: library part AVR

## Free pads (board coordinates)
  round 225 hole 130 unplated paste+0 mask-42.5: 0(250,250) 0(250,5750) 0(10725,5725) 0(10750,250)
  round 40 smd far side paste+0 mask+25: 0(450,5575) 0(525,500) 0(10525,425)
  round 40 smd paste+0 mask+25: 0(450,5575) 0(525,500) 0(10525,425)
  rect 37.4x39.4 smd paste-10000 mask+2: 0(7885,2127) 0(8115,3873)

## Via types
v1: diameter 30, hole 10, TopLayer to BottomLayer, tented both sides, 493 vias
v2: diameter 18, hole 8, TopLayer to BottomLayer, tented both sides, 308 vias
v3: diameter 18, hole 8, TopLayer to BottomLayer, tented bottom, 60 vias

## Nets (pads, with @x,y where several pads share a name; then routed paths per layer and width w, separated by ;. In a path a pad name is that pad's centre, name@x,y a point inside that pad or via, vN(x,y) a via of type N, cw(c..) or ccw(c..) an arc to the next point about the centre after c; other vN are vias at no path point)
3.3V: C126.2 C128.2 C129.2 C130.2 C131.2 C151.1 J13.1 J19.1 R31.2 R46.2 R47.2 R48.2 R55.2 R56.2 R57.2 R58.1 R59.2 R60.2 R61.2 R62.1 R63.2 R64.2 R74.2 R78.1 U9.1 U10.1 U10.23 U10.24 U11.1 | length 6405.7
  TopLayer w12: v1(9679,3080) 9689.3,3069.7 U11.1@9689.3,3047.2
  TopLayer w20: 10282,3515 10282.3,3515.3 R74.2@10282.3,4975 ; R48.2@10717.7,620 R47.2@10717.7,720 10717.7,929.7 10718,930
  TopLayer w25: 10389,1058 10442,1058 J19.1@10475,1025
  TopLayer w32: 10417.4,967.4 J19.1@10475,1025 10532.6,967.4 ; 10439.9,3389.9 J13.1@10500,3450 10439.9,3510.1
  MidLayer2 w25: v1(7305,3156) 8660,3156 8726,3090 v1(8972.3,3090)
  BottomLayer w12: v1(8972.3,2790) R56.2@9012.3,2790 ; v1(8972.3,2850) R57.2@9012.3,2850 ; v1(8972.3,2910) R58.1@9012.3,2910 ; v1(8972.3,2970) R59.2@9012.3,2970 ; v1(8972.3,3030) R60.2@9012.3,3030 ; v1(8972.3,3090) R61.2@9012.3,3090 ; v1(8972.3,3150) R62.1@9012.3,3150 ; v1(8972.3,3210) R63.2@9012.3,3210 ; U10.1@9183.9,2859.3 9200,2843.2 v1(9200,2824) C130.2@9200,2792.7 ; v1(9240,2717.3) 9250,2727.3 R64.2@9250,2757.3 ; C129.2@9350,2792.7 9350,2854.3 v1(9355,2859.3) ; C128.2@9400,2792.7 v1(9400,2826) ; U10.24@9416.1,2859.3 v1(9355,2859.3) ; U10.23@9416.1,2884.8 9363.8,2884.8 9355,2876 v1(9355,2859.3) ; v1(9679,3080) 9707.3,3051.7 C151.1@9707.3,3050
  BottomLayer w25: v1(7305,3156) 7305,3822.7 R31.2@7357.3,3875 ; R46.2@8642.7,1725 9508,1725 9560,1777 v1(9560,1845)
  other v1: 9605,1880 9560,1905 9605,1940 9560,1970 9605,2005 9560,2035 9605,2065
AGND1: C44.1 J17.3 NT2.2 R39.2 R44.1 R54.2 U7.7 U7.22 | length 462.5
  TopLayer w12: v1(7746,4060) R39.2@7782.3,4060 ; U7.7@8102.4,4085.6 8103.6,4085.6 8121,4103 v1(8141,4103) 8145.7,4107.7 C44.1@8180,4107.7
  MidLayer2 w32: 7444.3,3734.3 J17.3@7490,3780 ; 7444.3,3825.7 J17.3@7490,3780 ; 7535.7,3734.3 J17.3@7490,3780 ; 7535.7,3825.7 J17.3@7490,3780
  BottomLayer w12: v1(7317.3,3975) R54.2@7357.3,3975 ; v1(8141,4103) 8145.7,4107.7 R44.1@8180,4107.7
  other v2: 8018,4029 8036,4030 8054,4030 8027,4039 8045,4039 8063,4039 8009,4040
AGND2: C117.1 J14.3 NT1.1 R38.2 R51.2 R53.1 U8.7 U8.22 | length 456.5
  TopLayer w12: C117.1@7820,1892.3 7854.3,1892.3 v1(7859,1897) 7880.2,1897 U8.7@7897.6,1914.4 ; R51.2@8217.7,1940 v1(8253,1940)
  MidLayer2 w32: 8474.3,1769.3 J14.3@8520,1815 ; 8474.3,1860.7 J14.3@8520,1815 ; 8565.7,1769.3 J14.3@8520,1815 ; 8565.7,1860.7 J14.3@8520,1815
  BottomLayer w12: R53.1@7820,1892.3 7854.3,1892.3 v1(7859,1897) ; R38.2@8642.7,1625 v1(8677.7,1625)
  other v2: 7991,1960 7937,1961 7955,1961 7973,1961 7946,1970 7964,1970 7982,1971
CTRL: J13.2 SW2.2 | length 1839.1
  BottomLayer w12: SW2.2@10525,1900 10857,2232 10857,3270 10677,3450 J13.2@10600,3450
EN1: J13.20 SW3.1 U1.3 | length 11817.6
  TopLayer w12: U1.3@2053.1,3989.2 2093.8,3989.2 2102,3981 2152,3981 v1(2206,3927) ; v1(10360.5,4520) SW3.1@10435.5,4520 10634,4520 10703,4451 10703,3771 10930,3544 10930,2880 J13.20@10600,2550
  MidLayer2 w12: v1(2206,3927) 2578,3927 3260,3245 v1(8490,3245)
  BottomLayer w12: v1(8490,3245) 8490,3537 9473,4520 v1(10360.5,4520)
EN2: J13.18 SW3.2 U2.3 | length 9244
  TopLayer w12: U2.3@4053.1,3989.2 4093.8,3989.2 4102,3981 4152,3981 v1(4206,3927) ; v1(10360.5,4420) SW3.2@10435.5,4420 10629,4420 10672,4377 10672,3750 10887,3535 10887,2937 J13.18@10600,2650
  MidLayer2 w12: v1(4206,3927) 4967,3927 5501,3393 v1(8612,3393)
  BottomLayer w12: v1(8612,3393) 9639,4420 v1(10360.5,4420)
EN3: J13.16 SW3.3 U3.3 | length 7319.4
  TopLayer w12: U3.3@6053.1,3989.2 6093.8,3989.2 6100,3983 6150,3983 v1(6206,3927) ; v1(10360,4320) SW3.3@10435.5,4320 10590,4320 10641,4269 10641,3731 10845,3527 10845,2995 J13.16@10600,2750
  MidLayer2 w12: v1(6206,3927) 6977,3927 7320,3584 v1(8687,3584)
  BottomLayer w12: v1(8687,3584) 8562,3459 8562,3354 8599,3317 8695,3317 9698,4320 v1(10360,4320)
EN4: J13.14 SW3.4 U4.3 | length 11404.1
  TopLayer w12: v1(1828,2072) 1828,2053 1861.6,2019.4 1897.6,2019.4 1906.2,2010.8 U4.3@1946.9,2010.8 ; SW3.4@10435.5,4220 10580,4220 10608,4192 10608,3710 10799,3519 10799,3049 J13.14@10600,2850
  MidLayer2 w12: v1(1828,2072) 1800,2100 1800,2165 2521,2886 v1(8543,2886)
  BottomLayer w12: v1(8543,2886) 8543,2691 8660,2574 10168,2574 10393,2799 10549,2799 J13.14@10600,2850
EN5: J13.12 SW3.5 U5.3 | length 8877.2
  TopLayer w12: v1(3828,2072) 3828,2053 3858,2023 3898,2023 3910.2,2010.8 U5.3@3946.9,2010.8 ; SW3.5@10435.5,4120 10542,4120 10579,4083 10579,3686 10757,3508 10757,3107 J13.12@10600,2950
  MidLayer2 w12: v1(3828,2072) 3798,2102 3798,2159 4367,2728 8303,2728 8378,2653 v1(8670,2653)
  BottomLayer w12: v1(8670,2653) 10155,2653 10403,2901 10551,2901 J13.12@10600,2950
EN6: J13.10 SW3.6 U6.3 | length 7057.2
  TopLayer w12: v1(5828,2072) 5828,2053 5861.6,2019.4 5897.6,2019.4 5906.2,2010.8 U6.3@5946.9,2010.8 ; SW3.6@10435.5,4020 10530,4020 10546,4004 10546,3667 10714,3499 10714,3164 J13.10@10600,3050
  MidLayer2 w12: v1(5828,2072) 5799,2101 5799,2179 6142,2522 8205,2522 8239,2488 v1(8666,2488)
  BottomLayer w12: v1(8666,2488) 10633,2488 10668,2523 10668,2982 J13.10@10600,3050
EN7: J13.8 SW3.7 U7.3 | length 3293.8
  TopLayer w12: U7.3@8102.4,3971.5 8121.5,3971.5 8154,3939 v1(8268,3939) ; v1(10335,3920) SW3.7@10435.5,3920 10505,3920 10514,3911 10514,3644 10673,3485 10673,3223 J13.8@10600,3150
  MidLayer2 w12: v1(8268,3939) 8287,3920 v1(10335,3920)
EN8: J13.4 SW3.8 U8.3 | length 4952.9
  TopLayer w12: v1(7717,2115) 7717,2080 7726,2071 7835.5,2071 7864.9,2041.6 7864.9,2041.4 7873.1,2033.2 7892.9,2033.2 U8.3@7897.6,2028.5 ; SW3.8@10435.5,3820 10435.5,3654 10550,3539.5 10550,3400 J13.4@10600,3350
  MidLayer2 w12: v1(7717,2115) 7717,2186 7896,2365 v1(8662,2365)
  BottomLayer w12: v1(8662,2365) 9080,2365 9142,2427 10711,2427 10764,2480 10764,3186 J13.4@10600,3350
GPI: U11.2
GPIO: U11.20
LED1: D1.1 U10.21 U11.12 | length 912.1
  TopLayer w9: U11.12@9760.7,2968.5 9784.5,2968.5 9799,2954 9799,2886 v1(9890,2795) 9919,2766 9942.5,2766 D1.1@9968.5,2740
  BottomLayer w12: U10.21@9416.1,2936 9464,2936 9474,2926 9474,2862 9516,2820 9865,2820 v1(9890,2795)
LED2: D2.1 U10.20 U11.13 | length 843.3
  TopLayer w9: U11.13@9755,2984.3 9795.7,2984.3 9818,2962 9818,2927 v1(9890,2855) 9930,2815 D2.1@9968.5,2815
  BottomLayer w12: U10.20@9416.1,2961.6 9475.4,2961.6 9495,2942 9495,2906 9520,2881 9864,2881 v1(9890,2855)
LED3: D3.1 U10.19 U11.14 | length 775.5
  TopLayer w9: U11.14@9755,3000 9806,3000 9834,2972 9834,2971 v1(9890,2915) 9915,2890 D3.1@9968.5,2890
  BottomLayer w12: U10.19@9416.1,2987.2 9479.8,2987.2 9527,2940 9575,2940 9589.5,2954.5 9850.5,2954.5 v1(9890,2915)
LED4: D4.1 U10.18 U11.15 | length 724.1
  TopLayer w9: U11.15@9755,3015.7 9849.3,3015.7 v1(9890,2975) 9900,2965 D4.1@9968.5,2965
  BottomLayer w12: U10.18@9416.1,3012.8 9514.2,3012.8 9526,3001 9573,3001 9585,2989 9876,2989 v1(9890,2975)
LED5: D5.1 U10.17 U11.16 | length 717.8
  TopLayer w9: U11.16@9760.7,3031.5 9886.5,3031.5 v1(9890,3035)
  TopLayer w12: v1(9890,3035) 9895,3040 D5.1@9968.5,3040
  BottomLayer w12: U10.17@9416.1,3038.4 9485.4,3038.4 9507,3060 9581,3060 9622,3019 9874,3019 v1(9890,3035)
LED6: D6.1 U10.16 U11.17 | length 753.3
  TopLayer w9: U11.17@9760.7,3047.2 9842.2,3047.2 v1(9890,3095)
  TopLayer w12: v1(9890,3095) 9910,3115 D6.1@9968.5,3115
  BottomLayer w12: U10.16@9416.1,3064 9479,3064 9500,3085 9500,3102 9518,3120 9865,3120 v1(9890,3095)
LED7: D7.1 U10.15 U11.18 | length 846.9
  TopLayer w9: U11.18@9740.7,3049.7 9740.7,3084.7 9788,3132 9867,3132 v1(9890,3155)
  TopLayer w12: v1(9890,3155) 9925,3190 D7.1@9968.5,3190
  BottomLayer w12: U10.15@9416.1,3089.6 9458.6,3089.6 9499,3130 9499,3162 9517,3180 9865,3180 v1(9890,3155)
LED8: D8.1 U10.14 U11.19 | length 938.6
  TopLayer w9: U11.19@9725,3049.7 9725,3098 9779,3152 9827,3152 v1(9890,3215)
  TopLayer w12: v1(9890,3215) 9940,3265 D8.1@9968.5,3265
  BottomLayer w12: U10.14@9416.1,3115.2 9454.2,3115.2 9472,3133 9472,3197 9520,3245 9860,3245 v1(9890,3215)
N106541: C9.2 R4.1 U2.11 | length 140.2
  TopLayer w12: C9.2@3860,3993.5 3881.5,3972 v2(3903,3972) 3920.2,3989.2 U2.11@3946.9,3989.2
  BottomLayer w12: R4.1@3902.3,3935 3902.3,3971.3 v2(3903,3972)
N109036: C132.2 U2.10 | length 75.4
  TopLayer w12: v2(3900,4010.8) U2.10@3946.9,4010.8
  BottomLayer w12: v2(3900,4010.8) 3908.5,4002.3 C132.2@3925,4002.3
N111800: C15.2 R7.1 U3.11 | length 140.2
  TopLayer w12: C15.2@5860,3993.5 5881.5,3972 v2(5903,3972) 5920.2,3989.2 U3.11@5946.9,3989.2
  BottomLayer w12: R7.1@5902.3,3935 5902.3,3971.3 v2(5903,3972)
N112773: C3.2 R1.1 U1.11 | length 140.2
  TopLayer w12: C3.2@1860,3993.5 1881.5,3972 v2(1903,3972) 1920.2,3989.2 U1.11@1946.9,3989.2
  BottomLayer w12: R1.1@1902.3,3935 1902.3,3971.3 v2(1903,3972)
N113813: C21.2 R10.1 U4.11 | length 140.2
  TopLayer w12: U4.11@2053.1,2010.8 2079.8,2010.8 v2(2097,2028) 2118.5,2028 C21.2@2140,2006.5
  BottomLayer w12: v2(2097,2028) 2097.7,2028.7 R10.1@2097.7,2065
N124020: R6.2 U2.6 | length 38.7
  TopLayer w12: U2.6@4053.1,4054.1 4076.4,4054.1 R6.2@4087.3,4065
N125365: R3.2 U1.6 | length 38.7
  TopLayer w12: U1.6@2053.1,4054.1 2076.4,4054.1 R3.2@2087.3,4065
N125599: R12.2 U4.6 | length 38.7
  TopLayer w12: R12.2@1912.7,1935 1923.6,1945.9 U4.6@1946.9,1945.9
N125833: R9.2 U3.6 | length 38.7
  TopLayer w12: U3.6@6053.1,4054.1 6076.4,4054.1 R9.2@6087.3,4065
N143732: C29.2 R21.1 U5.11 | length 140.2
  TopLayer w12: U5.11@4053.1,2010.8 4079.8,2010.8 v2(4097,2028) 4118.5,2028 C29.2@4140,2006.5
  BottomLayer w12: v2(4097,2028) 4097.7,2028.7 R21.1@4097.7,2065
N143740: C30.2 R22.1 U6.11 | length 140.2
  TopLayer w12: U6.11@6053.1,2010.8 6079.8,2010.8 v2(6097,2028) 6118.5,2028 C30.2@6140,2006.5
  BottomLayer w12: v2(6097,2028) 6097.7,2028.7 R22.1@6097.7,2065
N143880: R23.2 U5.6 | length 38.7
  TopLayer w12: R23.2@3912.7,1935 3923.6,1945.9 U5.6@3946.9,1945.9
N143888: R24.2 U6.6 | length 38.7
  TopLayer w12: R24.2@5912.7,1935 5923.6,1945.9 U6.6@5946.9,1945.9
N983153: C42.2 U7.17
  other v2: 7992,3905 8008,3905 7999,3913
N983255: C42.1 U7.15
  other v2: 7820,3864 7840,3864 7820,3884 7840,3884 7820,3904 7840,3904
N983335: C43.2 R27.2 U7.2 | length 153.7
  TopLayer w12: U7.2@8102.4,3942.9 8121.2,3942.9 8173.5,3890.6 C43.2@8173.5,3885 8172.7,3884.2 R27.2@8172.7,3830
N983701: C45.2 R36.2 U7.4 | length 124
  TopLayer w12: U7.4@8102.4,4000 C45.2@8162.3,4000 v1(8162.3,3972.3)
  BottomLayer w12: R36.2@8130,3982.3 8140,3972.3 v1(8162.3,3972.3)
N983781: C44.2 R36.1 U7.5 | length 175.8
  TopLayer w12: U7.5@8102.4,4028.5 8174.5,4028.5 8180,4034 v1(8180,4036) C44.2@8180,4072.3
  BottomLayer w12: R36.1@8130,4017.7 8138.7,4017.7 8150,4029 8173,4029 v1(8180,4036)
N983905: R39.1 U7.10 | length 81.1
  TopLayer w12: R39.1@7817.7,4060 7872.9,4060 7875.8,4057.1 U7.10@7897.6,4057.1
N983923: C51.2 R42.2 R44.2 U7.6 | length 251.2
  TopLayer w12: U7.6@8102.4,4057.1 8137.1,4057.1 v1(8139.5,4059.5)
  BottomLayer w12: v1(8139.5,4059.5) 8152.3,4072.3 R44.2@8180,4072.3 8207.3,4072.3 8216,4081 8216,4137.1 8208.1,4145 C51.2@8187.7,4145 R42.2@8187.7,4185
N1133327: C114.2 U8.17
  other v2: 8001,2087 7992,2095 8008,2095
N1133411: C114.1 U8.15
  other v2: 8160,2096 8180,2096 8160,2116 8180,2116 8160,2136 8180,2136
N1133439: C115.2 R45.2 U8.2 | length 156.6
  TopLayer w12: R45.2@7827.3,2170 7827.3,2115.8 C115.2@7826.5,2115 7826.5,2104.8 7840.3,2091 7844.1,2091 7864.9,2070.2 7864.9,2069.9 7873.1,2061.7 7873.4,2061.7 7878,2057.1 U8.2@7897.6,2057.1
N1133683: C116.2 R50.2 U8.4 | length 124
  TopLayer w12: v1(7837.7,2027.7) C116.2@7837.7,2000 U8.4@7897.6,2000
  BottomLayer w12: v1(7837.7,2027.7) 7860,2027.7 R50.2@7870,2017.7
N1133735: C117.2 R50.1 U8.5 | length 175.8
  TopLayer w12: C117.2@7820,1927.7 v1(7820,1964) 7820,1966 7825.5,1971.5 U8.5@7897.6,1971.5
  BottomLayer w12: v1(7820,1964) 7827,1971 7858.7,1971 R50.1@7870,1982.3
N1133791: R51.1 U8.10 | length 81.1
  TopLayer w12: U8.10@8102.4,1942.9 8124.2,1942.9 8127.1,1940 R51.1@8182.3,1940
N1133799: C121.2 R52.2 R53.2 U8.6 | length 256.5
  TopLayer w12: v1(7860.5,1940.5) 7862.9,1942.9 U8.6@7897.6,1942.9
  BottomLayer w12: R52.2@7812.3,1815 C121.2@7812.3,1855 7789.9,1855 7781.1,1863.8 7781.1,1919.1 7789.7,1927.7 R53.2@7820,1927.7 7847.7,1927.7 v1(7860.5,1940.5)
N1144589: SW1.2 SW3.9 SW3.10 SW3.11 SW3.12 SW3.13 SW3.14 SW3.15 SW3.16 | length 2103.6
  TopLayer w12: SW1.2@10525,5160 10615,5070 10615,4651.1 10746.1,4520 SW3.16@10774.5,4520 10832,4520 10854,4498 10854,4427 10847,4420 ; SW3.9@10774.5,3820 10854,3820 10864,3830 10864,3908 10852,3920 ; SW3.10@10774.5,3920 10852,3920 ; SW3.11@10774.5,4020 10842,4020 ; SW3.12@10774.5,4120 10840,4120 ; SW3.13@10774.5,4220 10843,4220 ; SW3.14@10774.5,4320 10836,4320 ; SW3.15@10774.5,4420 10847,4420 ; 10836,4320 10860,4344 10860,4407 10847,4420 ; 10836,4320 10859,4297 10859,4236 10843,4220 ; 10840,4120 10860,4140 10860,4203 10843,4220 ; 10840,4120 10860,4100 10860,4038 10842,4020 ; 10842,4020 10859,4003 10859,3927 10852,3920
N1166950: R75.1 SW2.3 | length 186.4
  TopLayer w12: R75.1@10342.7,2075 10515,2075 SW2.3@10525,2085
N1167645: R55.1 SW2.1 | length 186.4
  TopLayer w12: R55.1@10342.7,1725 10352.7,1715 SW2.1@10525,1715
N1170426: R64.1 U10.2 | length 147.8
  BottomLayer w12: U10.2@9183.9,2884.8 9232.2,2884.8 9250,2867 R64.1@9250,2792.7
N1170926: D5.2 R70.2 | length 75.8
  TopLayer w12: D5.2@10031.5,3040 R70.2@10107.3,3040
N1170982: D4.2 R69.2 | length 75.8
  TopLayer w12: D4.2@10031.5,2965 R69.2@10107.3,2965
N1171050: D3.2 R68.2 | length 75.8
  TopLayer w12: D3.2@10031.5,2890 R68.2@10107.3,2890
N1171118: D2.2 R67.2 | length 75.8
  TopLayer w12: D2.2@10031.5,2815 R67.2@10107.3,2815
N1171178: D1.2 R66.2 | length 75.8
  TopLayer w12: D1.2@10031.5,2740 R66.2@10107.3,2740
N1171210: R65.2 U10.22 | length 216.8
  BottomLayer w12: R65.2@9300,2792.7 9300,2881.4 9329,2910.4 U10.22@9416.1,2910.4
N1176310: D6.2 R71.2 | length 75.8
  TopLayer w12: D6.2@10031.5,3115 R71.2@10107.3,3115
N1183669: D8.2 R73.2 | length 75.8
  TopLayer w12: D8.2@10031.5,3265 R73.2@10107.3,3265
N1183969: D7.2 R72.2 | length 75.8
  TopLayer w12: D7.2@10031.5,3190 R72.2@10107.3,3190
N1197737: R74.1 SW1.1 | length 207.3
  TopLayer w12: R74.1@10317.7,4975 SW1.1@10525,4975
N1197747: R18.1 SW1.3 | length 207.3
  TopLayer w12: R18.1@10317.7,5345 SW1.3@10525,5345
N1234759: C134.2 U1.10 | length 75.4
  TopLayer w12: v2(1900,4010.8) U1.10@1946.9,4010.8
  BottomLayer w12: v2(1900,4010.8) 1908.5,4002.3 C134.2@1925,4002.3
N1235035: C135.2 U4.10 | length 75.4
  TopLayer w12: U4.10@2053.1,1989.2 v2(2100,1989.2)
  BottomLayer w12: C135.2@2075,1997.7 2091.5,1997.7 v2(2100,1989.2)
N1235784: C136.2 U6.10 | length 75.4
  TopLayer w12: U6.10@6053.1,1989.2 v2(6100,1989.2)
  BottomLayer w12: C136.2@6075,1997.7 6091.5,1997.7 v2(6100,1989.2)
N1236304: C137.2 U5.10 | length 75.4
  TopLayer w12: U5.10@4053.1,1989.2 v2(4100,1989.2)
  BottomLayer w12: C137.2@4075,1997.7 4091.5,1997.7 v2(4100,1989.2)
N1413705: J19.2 J20.1 R77.1 R78.2 | length 257.3
  TopLayer w12: J19.2@10575,1025 J20.1@10575,1125 R78.2@10657.3,1125 R77.1@10657.3,1200
OPT: J13.6 J20.2 J21.1 R76.1 R77.2 | length 2749.4
  TopLayer w12: J20.2@10475,1125 J21.1@10475,1225 10544,1294 10681,1294 10692.7,1282.3 R76.1@10692.7,1250 R77.2@10692.7,1200
  MidLayer2 w12: J21.1@10475,1225 10782,1532 10782,3219 10751,3250 J13.6@10600,3250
